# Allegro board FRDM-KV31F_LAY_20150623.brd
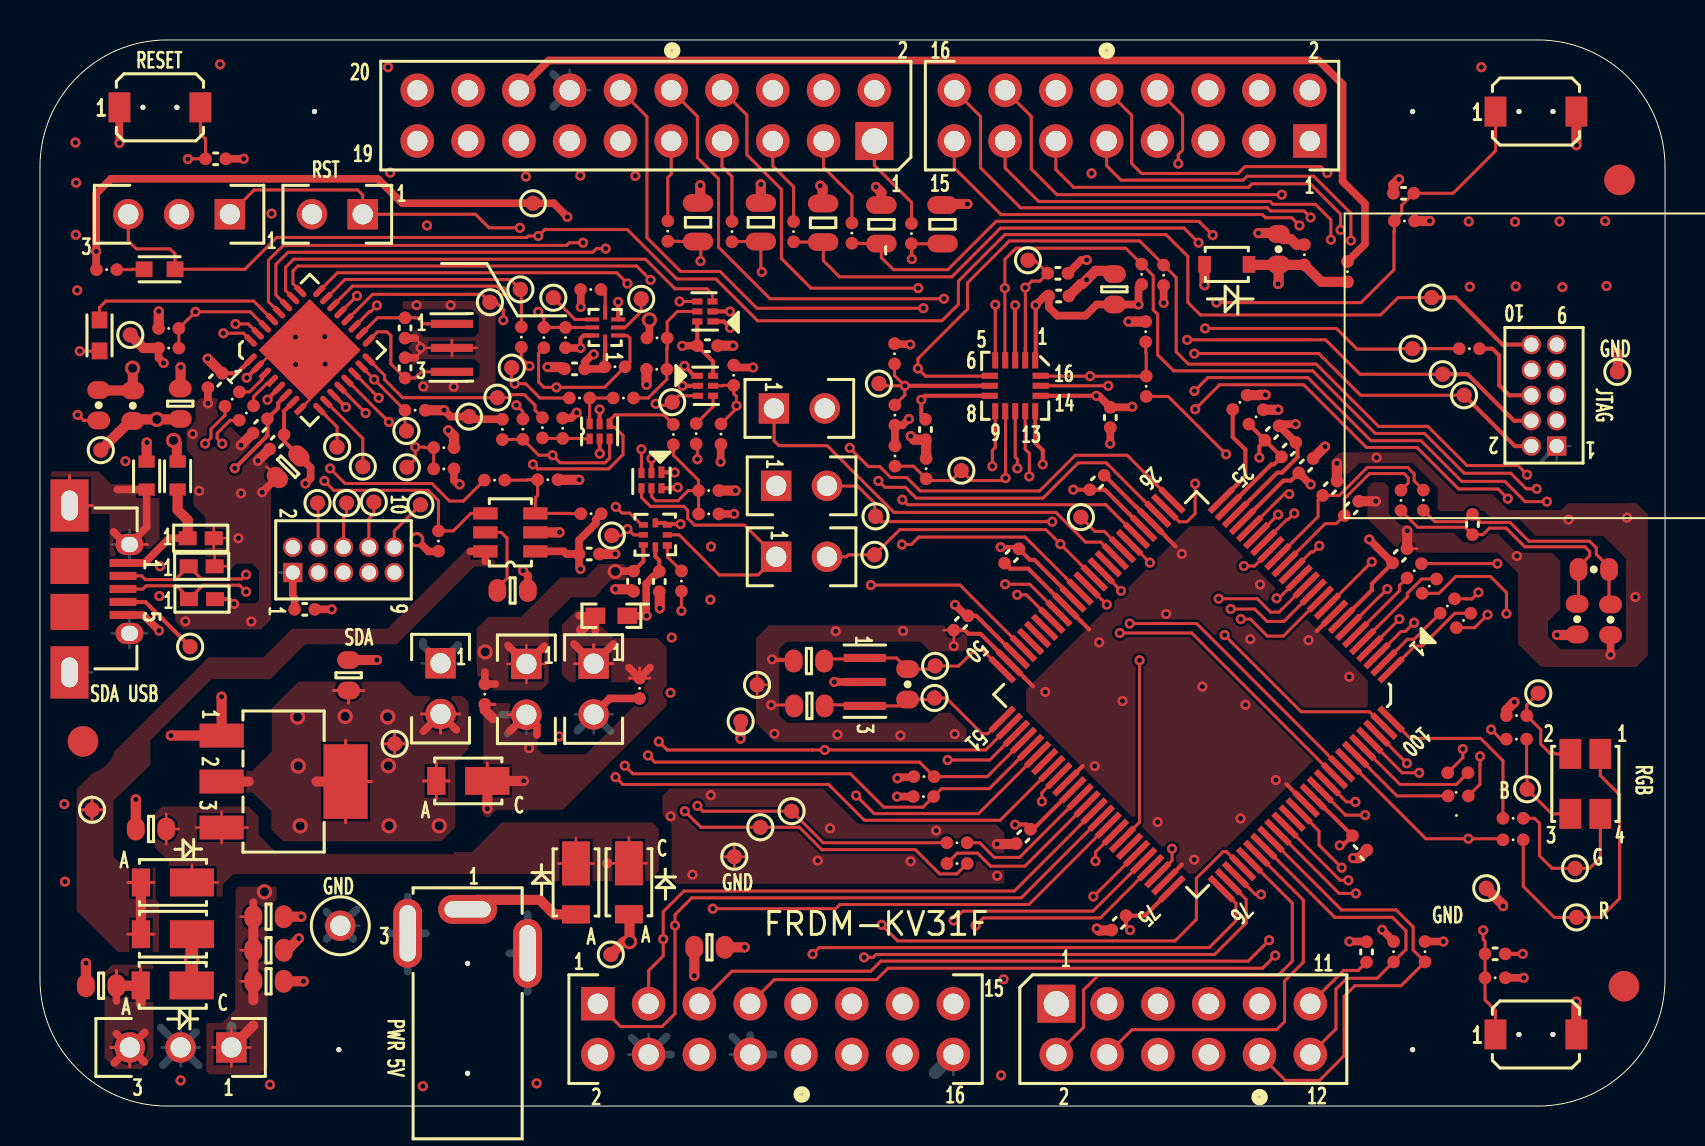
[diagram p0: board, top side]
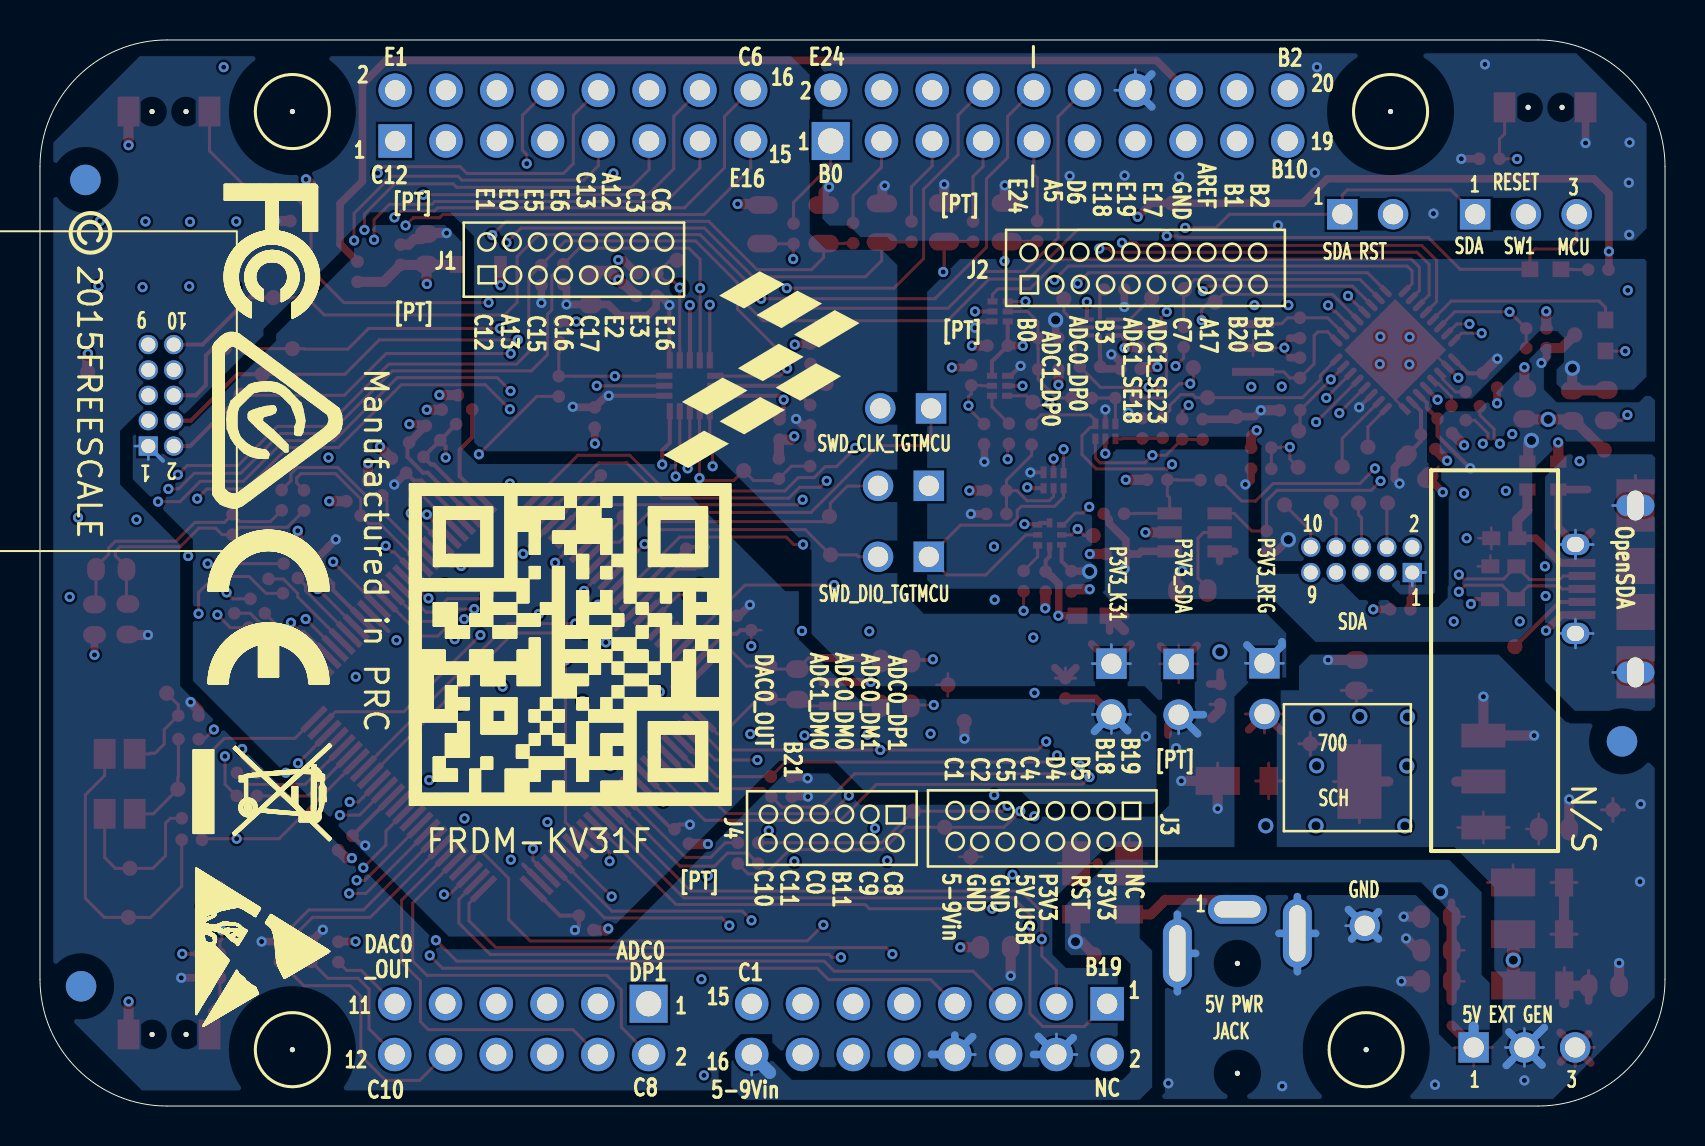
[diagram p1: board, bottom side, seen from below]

Outline 81.28 x 53.34 mm; copper layers: TOP, GND, INT_1, BOTTOM. Coordinates in mm from the lower left corner of the outline.
Outline path: 0,46.99 arc(1.86,51.48) 6.35,53.34 74.93,53.34 arc(79.42,51.48) 81.28,46.99 81.28,6.35 arc(79.42,1.86) 74.93,0 6.35,0 arc(1.86,1.86) 0,6.35 0,46.99

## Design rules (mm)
net group GA[0:7]: nets 8MHZ_EXTAL XTAL0
net group LEDRGB_BLUE: nets LEDRGB_BLUE PTE25
net group POW: nets P5V0_SDA_USB_CONN_VBUS VREFH
net group USB_SI_CONN_D: nets SDA_USB_CONN_DN SDA_USB_CONN_DP
net group USB_SI_D: nets SDA_USB_DN SDA_USB_DP
net group ANALOG: nets ADC0_DM1 ADC0_DP1 ADC1_DM1 ADC1_DP1 ADC1_SE18 DAC0_OUT PTB1 PTB10 PTC11
net group ANALOG_PH: nets PTB2 PTB3 PTB11
net group CLOCKS: nets LEDRGB_GREEN PTB18 PTC3 PTC6 PTC8 PTD1 PTE0 SDA_EXTAL SWD_CLK_TGTMCU SWD_CLK_TGTMCU_BUF
nets with their own width: min track width 0.127; nets GND

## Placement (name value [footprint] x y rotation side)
C1  10uF  [CC0402_25]  11.02 34.03 225 top
C2  1000pF  [CC0402_25]  8.79 47.39 0 top
C3  0.1UF  [CC0402_25]  50.91 41.67 0 top
C4  0.1UF  [CC0402_25]  50.95 40.53 0 top
C5  4.7uF  [CC0603_OV]  53.74 40.87 90 top
C6  22PF  [CC0402_25]  18.26 38.93 270 top
C7  0.1UF  [CC0402_25]  33.38 38.04 0 top
C8  0.1UF  [CC0402_25]  26.74 36.88 180 top
C9  22PF  [CC0402_25]  18.26 36.93 90 top
C10  0.1UF  [CC0402_25]  8.76 36.3 225 top
C11  2.2UF  [CC0603_OV]  7.02 35.14 90 top
C12  1.0UF  [CC0402_25]  11.85 33.23 225 top
C13  0.1UF  [CC0402_25]  44.29 33.85 270 top
C14  0.1UF  [CC0402_25]  53.54 34.45 270 top
C15  10uF  [CC0603_OV]  12.41 31.99 225 top
C16  0.1UF  [CC0402_25]  27.47 27.62 0 top
C17  4.7uF  [CC0402_25]  29.69 26.26 270 top
C18  0.1UF  [CC0402_25]  13.24 24.85 0 top
C19  18PF  [CC0603_OV]  23.64 25.79 180 top
C21  0.1UF  [CC0402_25]  71.65 29.1 90 top
C22  2200PF  [CC0402_25]  65.6 29.9 45 top
C23  4.7uF  [CC0402_25]  30.98 26.24 270 top
C24  0.1UF  [CC0402_25]  49.18 13.49 225 top
C25  0.1UF  [CC0402_25]  52.87 31.19 45 top
C26  0.1UF  [CC0402_25]  46.07 24.17 225 top
C27  0.1UF  [CC0402_25]  63.32 32.04 45 top
C28  0.1UF  [CC0402_25]  48.61 27.52 225 top
C29  0.1UF  [CC0402_25]  53.96 9.17 225 top
C30  0.1UF  [CC0402_25]  66.01 13.16 315 top
C32  0.01UF  [CC0402_25]  68.01 27.53 45 top
C33  0.01UF  [CC0402_25]  61.62 33.68 225 top
C34  0.1UF  [CC0402_25]  62.46 32.84 225 top
C35  2200PF  [CC0402_25]  64.52 30.91 45 top
C37  18PF  [CC0603_OV]  38.46 22.27 0 top
C38  18PF  [CC0603_OV]  38.48 20.02 0 top
C40  2.2UF  [CC0603_OV]  33.49 7.94 0 top
C41  10uF  [CC0603_OV]  5.55 13.86 180 top
C43  0.1UF  [CC0402_25]  66.35 7.71 90 top
C44  220PF  [CC0805_OV]  39.17 44.19 90 top
C50  10uF  [CC0603_OV]  11.43 9.47 0 top
C51  10uF  [CC0603_OV]  15.44 21.55 90 top
C52  10uF  [CC0603_OV]  11.43 7.79 0 top
C53  10uF  [CC0603_OV]  3.06 6.02 180 top
C54  10uF  [CC0603_OV]  11.43 6.24 0 top
C55  0.1UF  [CC0402_25]  72.79 7.61 0 top
C56  0.1UF  [CC0402_25]  68.2 45.67 180 top
C505  220PF  [CC0805_OV]  32.92 44.22 90 top
C507  220PF  [CC0805_OV]  42.09 44.12 90 top
C516  220PF  [CC0805_OV]  36.06 44.22 90 top
C522  220PF  [CC0805_OV]  45.14 44.12 90 top
D1  RED  [LED_0603]  5.98 41.87 0 top
D2  LED GREEN  [LED_0603]  2.98 38.56 90 top
D4  CLV1A-FKB-CJ1M1F1BB7R4S3  [LED4_3P4X3MM_SMT]  77.29 16.12 0 top
D5  DFLS130L-7  [POWERDI-123_3MMX2MM]  6.75 8.6 180 top
D6  DFLS130L-7  [POWERDI-123_3MMX2MM]  6.75 11.19 180 top
D7  3.0V  [SOD-323-A]  59.36 42.11 180 top
D9  DFLS130L-7  [POWERDI-123_3MMX2MM]  26.81 11.29 270 top
D10  DFLS130L-7  [POWERDI-123_3MMX2MM]  29.46 11.3 270 top
D11  DFLS130L-7  [POWERDI-123_3MMX2MM]  21.52 16.27 180 top
D13  DFLS130L-7  [POWERDI-123_3MMX2MM]  6.74 6.04 180 top
J1  CON_2X8  [HDR208_ESQ_SKT]  63.51 48.29 270 top
J2  SKT_2x10  [HDR210_ESQ_SKT]  41.73 48.29 270 top
J3  CON_2X8  [HDR208_ESQ_SKT]  27.9 5.12 90 top
J4  CON_2X6  [HDR206_ESQ_SKT]  50.84 5.12 90 top
J5  HDR 1X2 TH  [SH_HDR102_BOTTOM]  16.14 44.62 270 top
J6  MICRO USB AB 5  [CON5_MICROUSB]  1.48 25.87 270 top
J8  HDR 1X2 TH  [SH_HDR102_BOTTOM]  36.82 31.03 90 top
J9  HDR 2X5  [HDR_5X2_FTSH_TH_NSP]  75.86 33.02 180 top
J10  HDR 2X5  [HDR_5X2_FTSH_TH_NSP]  12.64 26.69 90 top
J11  HDR 1X2 TH  [SH_HDR102_BOTTOM]  36.71 34.9 90 top
J12  HDR 1X2 TH  [SH_HDR102_BOTTOM]  36.82 27.48 90 top
J18  HDR 1X2  [HDR102]  24.33 22.12 0 top
J19  HDR 1X2 TH  [SH_HDR102_BOTTOM]  20.04 22.15 0 top
J20  HDR 1X2 TH  [SH_HDR102_BOTTOM]  27.69 22.13 0 top
J24  CON PWR 3  [CON_JACK_PJ1_022_TH-RA]  21.39 9.84 90 top
J25  HDR_1X3  [HDR103]  9.5 44.62 270 top
J27  HDR_1X3  [HDR103]  9.57 2.93 270 top
L1  330 OHM  [IND_1608]  5.33 31.55 90 top
L2  330 OHM  [IND_1608]  6.88 31.55 90 top
NOREF  -  []  0 41.47 0 top
NOREF#2  -  []  65.19 -3.77 0 top
NOREF#3  -  []  65.19 -3.77 90 top
NOREF#4  -  []  28.92 39.36 90 top
NOREF#5  -  [unnamed#2]  79.23 5.99 0 top
NOREF#6  -  []  13.74 2.72 0 top
NOREF#7  -  []  70.32 0.01 90 top
NOREF#8  -  []  -16.59 -36.7 0 top
NOREF#9  -  []  -235.03 -179.13 0 top
NOREF#10  -  []  28.89 39.68 270 top
NOREF#11  -  []  39.19 48.29 0 top
NOREF#12  -  []  47.78 34.76 90 top
NOREF#13  -  []  79.64 51.25 0 top
NOREF#14  -  []  42.18 43.28 90 top
NOREF#15  -  []  47.5 36.04 90 top
NOREF#16  -  []  50.28 37.54 90 top
NOREF#17  -  []  47.78 34.76 0 top
NOREF#18  -  []  50.84 5.12 0 top
NOREF#19  -  []  18.87 48.29 90 top
NOREF#20  -  [unnamed#2]  79 46.34 0 top
NOREF#21  -  []  47.78 34.76 0 top
NOREF#22  -  []  50.84 5.12 0 top
NOREF#23  -  []  -381.97 185.27 0 top
NOREF#24  -  []  17.22 52.1 0 top
NOREF#25  -  []  47.78 34.76 0 top
NOREF#26  -  []  47.28 37.54 0 top
NOREF#27  -  []  50.26 40.54 0 top
NOREF#28  -  []  12.88 1.39 0 top
NOREF#29  -  []  24.14 10.61 0 top
NOREF#30  -  []  -408 -339.88 0 top
NOREF#31  -  []  13.74 2.72 0 top
NOREF#32  -  [unnamed#2]  2.15 18.24 0 top
NOREF#33  -  []  22.3 52.1 90 top
NOREF#34  -  []  145.04 65.17 0 top
NOREF#35  -  []  63.54 2.58 90 top
NOREF#36  -  []  28.92 38.96 270 top
NOREF#37  -  []  47.5 35.54 0 top
NOREF#38  -  []  18.87 48.29 0 top
NOREF#39  -  []  47.5 36.54 90 top
NOREF#40  -  []  54.66 12.88 180 bottom
NOREF#41  -  [unnamed#2]  13.73 49.76 180 bottom
NOREF#42  -  [unnamed#2]  68.66 2.82 180 bottom
NOREF#43  -  []  20.69 32.09 270 bottom
NOREF#44  -  []  55.65 13.45 180 bottom
NOREF#45  -  [unnamed#2]  14.95 2.82 180 bottom
NOREF#46  -  []  51.23 -43.91 270 bottom
NOREF#47  -  []  54.61 5.51 180 bottom
NOREF#48  -  []  76.38 -9.16 0 bottom
NOREF#49  -  [unnamed#2]  68.66 49.76 180 bottom
NOREF#50  -  [unnamed#2]  79.01 46.34 180 bottom
NOREF#51  -  [unnamed#2]  79.23 5.99 180 bottom
NOREF#52  -  []  91.82 39.52 180 bottom
NOREF#53  -  []  74.4 20.38 0 bottom
NOREF#54  -  [unnamed#2]  2.15 18.25 180 bottom
R1  10.0K  [RC0402_25]  68.25 44.28 180 top
R2  100  [RC0402_25]  3.34 41.85 0 top
R3  0  [RC0402_25]  24.08 38.47 90 top
R4  4.7K  [RC0402_25]  27.55 40.85 180 top
R5  4.7K  [RC0402_25]  20.2 31.88 180 top
R6  10.0K  [RC0402_25]  20.2 32.94 0 top
R7  10.0K  [RC0402_25]  6.44 38.91 180 top
R8  4.7K  [RC0402_25]  6.44 37.92 0 top
R9  4.7K  [RC0402_25]  55.1 41.62 90 top
R10  0  [RC0402_25]  25.2 38.45 90 top
R11  180K  [RC0402_25]  26.28 38.45 90 top
R12  4.7K  [RC0402_25]  30.86 38.43 0 top
R13  10.0K  [RC0402_25]  30.85 36.86 180 top
R14  10.0K  [RC0402_25]  28.76 36.99 0 top
R15  4.7K  [RC0402_25]  56.2 41.57 90 top
R16  10.0K  [RC0402_25]  34.7 36.57 90 top
R17  220  [RC0603_OV]  2.94 35.06 270 top
R18  0  [RC0402_25]  26.98 35.43 180 top
R19  0  [RC0402_25]  29.18 35.43 0 top
R20  33  [RC0402_25]  9.61 35.37 45 top
R21  10.0K  [RC0402_25]  18.76 34.81 180 top
R22  33  [RC0402_25]  10.32 34.67 45 top
R23  4.7K  [RC0402_25]  34.06 33.62 90 top
R24  0  [RC0402_25]  32.82 33.64 270 top
R25  0  [RC0402_25]  25.13 33.94 90 top
R26  10.0K  [RC0402_25]  26.14 33.91 270 top
R27  10.0K  [RC0402_25]  23.13 33.86 90 top
R28  0  [RC0402_25]  24.15 33.87 90 top
R29  1.0K  [RC0402_25]  22.74 31.32 0 top
R30  15K  [RC0402_25]  25.4 31.34 0 top
R31  10.0K  [RC0402_25]  42.74 37.64 90 top
R32  10.0K  [RC0402_25]  42.76 34.57 90 top
R33  0  [RC0402_25]  31.68 33.6 270 top
R34  10.0K  [RC0402_25]  27.56 29.64 180 top
R35  10.0K  [RC0402_25]  19.93 28.27 90 top
R36  0  [RC0603_OV]  4.64 35.04 270 top
R37  4.7K  [RC0402_25]  33.45 29.63 180 top
R38  0  [RC0402_25]  32.08 26.27 270 top
R39  10.0K  [RC0402_25]  33.45 30.79 0 top
R40  10.0K  [RC0402_25]  42.76 32.52 270 top
R41  4.7K  [RC0402_25]  44.19 15.48 0 top
R42  10.0K  [RC0402_25]  55.31 38.74 90 top
R43  10.0K  [RC0402_25]  44.32 31.89 90 top
R44  4.99K  [RC0603_OV]  78.55 24.33 270 top
R45  4.99K  [RC0603_OV]  76.89 24.36 90 top
R46  100  [RC0402_25]  69.19 30.31 270 top
R47  100  [RC0402_25]  68.07 30.3 270 top
R48  4.7K  [RC0402_25]  44.21 16.48 0 top
R49  4.7K  [RC0402_25]  69.28 7.72 270 top
R50  4.7K  [RC0402_25]  67.7 7.72 270 top
R52  1.0M  [RC0603_OV]  43.4 21.1 270 top
R53  0  [RC0402_25]  65.4 41.74 90 top
R54  0  [RC0402_25]  45.86 13.17 180 top
R55  0  [RC0402_25]  45.87 12.13 180 top
R56  0  [RC0402_25]  70.94 15.52 0 top
R57  0  [RC0402_25]  70.92 16.67 0 top
R58  0  [RC0402_25]  71.2 24.3 225 top
R59  0  [RC0402_25]  70.39 25.02 225 top
R60  0  [RC0402_25]  60.02 35.21 45 top
R61  0  [RC0402_25]  22.25 20.61 90 top
R62  0  [RC0402_25]  60.83 34.48 225 top
R63  10  [RC0402_25]  29.99 20.9 270 top
R64  0  [RC0402_25]  55.33 36.01 270 top
R65  0  [RC0402_25]  68.74 26.78 225 top
R66  1K  [RC0603_OV]  61.95 42.87 270 top
R67  0  [RC0402_25]  69.49 26.01 225 top
R68  0  [RC0402_25]  63.24 42.59 270 top
R69  576  [RC0402_25]  73.68 13.32 0 top
R73  270  [RC0402_25]  73.85 18.36 180 top
R74  270  [RC0402_25]  73.68 14.4 180 top
R75  10.0K  [RC0402_25]  72.79 6.42 180 top
R76  100  [RC0402_25]  37.69 43.75 90 top
R80  0  [RC0402_25]  71.49 37.89 180 top
R88  130  [RC0402_25]  73.86 19.54 0 top
R534  100  [RC0402_25]  31.4 43.78 90 top
R549  100  [RC0402_25]  34.61 43.75 90 top
R551  100  [RC0402_25]  40.61 43.68 90 top
R555  100  [RC0402_25]  43.59 43.65 90 top
RT1  10K  [RC0603_OV]  77.72 26.85 0 top
SH1  0  [SH0603]  28.58 24.53 180 top
SW1  SW2_STM151XX  [SW2_4X3MM_SM]  6 49.97 0 top
SW2  SW2_STM151XX  [SW2_4X3MM_SM]  74.83 49.76 0 top
SW3  SW2_STM151XX  [SW2_4X3MM_SM]  74.82 3.58 0 top
TP1  -  [TPAD_030]  24.03 40.86 0 top
TP2  -  [TPAD_030]  25.68 40.44 270 top
TP3  -  [TPAD_030]  30.07 40.39 270 top
TP4  -  [TPAD_030]  49.42 42.32 270 top
TP5  -  [TPAD_030]  18.35 31.96 0 top
TP6  -  [TPAD_030]  23.6 36.94 0 top
TP7  -  [TPAD_030]  7.51 22.98 0 top
TP8  -  [TPAD_030]  41.96 36.15 270 top
TP9  -  [TPAD_030]  16.15 31.99 0 top
TP10  -  [TPAD_030]  14.86 32.97 0 top
TP11  -  [TPAD_030]  46.08 31.79 270 top
TP12  -  [TPAD_030]  4.52 38.58 0 top
TP13  -  [TPAD_030]  76.86 9.44 270 top
TP14  -  [TPAD_030]  74.38 15.85 270 top
TP15  -  [TPAD_030]  3.04 32.82 0 top
TP16  TEST POINT WHITE  [TEST_LOOP]  15.02 9.02 0 top
TP17  -  [TPAD_030]  76.78 11.89 270 top
TP18  -  [TPAD_030]  52.06 29.47 0 top
TP19  -  [TPAD_030]  2.6 14.82 0 top
TP20  -  [TPAD_030]  28.55 7.58 0 top
TP21  -  [TPAD_030]  35.87 21.07 0 top
TP22  -  [TPAD_030]  72.34 10.9 0 top
TP23  -  [TPAD_030]  78.89 36.73 0 top
TP24  -  [TPAD_030]  34.73 12.47 0 top
TP25  -  [TPAD_030]  18.33 33.78 0 top
TP26  -  [TPAD_030]  13.88 30.17 0 top
TP27  -  [TPAD_030]  15.33 30.17 0 top
TP28  -  [TPAD_030]  16.7 30.21 0 top
TP29  -  [TPAD_030]  19.03 30.08 0 top
TP30  -  [TPAD_030]  71.23 35.56 0 top
TP31  -  [TPAD_030]  70.16 36.62 0 top
TP32  -  [TPAD_030]  68.65 37.89 0 top
TP33  -  [TPAD_030]  69.61 40.45 0 top
TP35  -  [TPAD_030]  44.78 22.02 0 top
TP36  -  [TPAD_030]  44.74 20.42 0 top
TP37  -  [TPAD_030]  35.05 19.25 0 top
TP38  -  [TPAD_030]  21.46 34.5 0 top
TP39  -  [TPAD_030]  37.59 14.75 0 top
TP40  -  [TPAD_030]  36.03 13.95 0 top
TP41  -  [TPAD_030]  41.74 27.58 0 top
TP42  -  [TPAD_030]  41.79 29.5 0 top
TP43  -  [TPAD_030]  74.94 20.65 0 top
TP44  -  [TPAD_030]  24.66 45.17 0 top
TP48  -  [TPAD_030]  28.6 28.54 0 top
TP49  -  [TPAD_030]  31.62 35.22 0 top
TP50  -  [TPAD_030]  22.5 40.22 0 top
TP52  -  [TPAD_030]  22.88 35.44 0 top
TP56  -  [TPAD_030]  17.74 18.13 0 top
U1  0402ESDA-MLP  [0402_MLP]  8.04 28.41 0 top
U2  74LVCH1T45  [UDFN6_1X1P5MM]  33.26 39.76 180 top
U3  NTSX2102GU8H  [XQFN8_1P45X1P25MM]  28.27 38.96 90 top
U4  0402ESDA-MLP  [0402_MLP]  8.09 27.01 0 top
U5  MK20DX128VFM5  [QFN32_S142EP]  13.49 37.83 45 top
U6  0402ESDA-MLP  [0402_MLP]  8.1 25.36 0 top
U7  74LVCH1T45  [UDFN6_1X1P5MM]  33.28 36.04 0 top
U8  FXOS8700CQ  [QFN5X3_0P5_3X3]  48.78 36.04 270 top
U9  NLX2G14  [ULLGA6_1P45X1_0P5MM]  27.99 33.76 90 top
U10  74LVC2T45GM,125  [QFN8_1P6X1P6MM]  30.78 28.58 180 top
U11  MIC2005-0.8YM6  [SOT23-6_A]  23.53 28.7 180 top
U12  74LVCH1T45  [UDFN6_1X1P5MM]  30.58 31.29 270 top
U13  MKV31F512VLL12  [LQFP100_0P5_14X14]  57.85 20.59 225 top
U17  NCP1117ST33T3G  [SOT223]  12.18 16.24 270 top
X501  8.00MHZ  [XTAL3_3P35X1P45_SM]  41.25 21.22 90 top
Y1  8.00MHZ  [XTAL3_3P35X1P45_SM]  20.6 37.93 90 top

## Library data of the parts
C1-C6 C9 C11-C14 C21 C22 C35 C40 C41 C44 C50-C56 C505 C507 C516 C522 = CAP_NP
C7 C8 C10 C15-C18 C23-C30 C34 C43 = CAP_NP: tolerance: 10%
C19 C37 C38 = CAP_NP: tolerance: 5%
C32 C33 = CAP_NP: tolerance: 20%
D1 D2 = LED
D4 = CLV1A_LED_4P
D5 D6 D9-D11 D13 = DIODE_SCHTKY
D7 = ZDIODE
J1 J3 = CONN_HDR_8X2
J2 = CONN_HDR_10X2
J4 = CONN_HDR_6X2
J5 J8 J11 J12 J18-J20 = CONN_HDR_2X1
J6 = USB_MINI_AB_RECEPTACLE
J9 J10 = CONN_HDR_5X2
J24 = DC POWER JACK
J25 J27 = CONN_HDR_3X1
L1 L2 = BEAD
R1 R2 R4 R5 R8 R9 R12 R15 R23 R29 R30 R34 R35 R37 R41 R48-R50 R54-R59 R65 R67 R75 R76 R534 R549 R551 R555 = RES: tolerance: 1%
R3 R6 R7 R11 R17-R22 R25 R28 R31-R33 R36 R40 R42-R47 R53 R60-R64 R66 R68 R69 R74 R80 R88 = RES
R10 R13 R14 R16 R24 R26 R27 R38 R39 R52 = RES: tolerance: 5%
R73 = RES: signal model: DEFAULT_RESISTOR_330.000000OHM_2_1
RT1 = THERMISTOR
SH1 = RES_SHORT-2
SW1-SW3 = SW2_STM151XX
TP1-TP33 TP35-TP44 TP48-TP50 TP52 TP56 = TestLoop
U1 U4 U6 = DIODE_TVS_BIDIR
U2 U7 U12 = 74LVCH1T45_6P
U3 = NTSX2102GU8H_8P
U5 = PK20DX128V_QFN_32P
U8 = FXOS8700CQ_QFN_16P
U9 = NLU2GU04
U10 = 74LVC2T45GM_8P
U11 = MIC2005-0.8YM6
U13 = MKV10FN_LQFP_100P
U17 = LD1117AS18
X501 Y1 = XTAL_CS

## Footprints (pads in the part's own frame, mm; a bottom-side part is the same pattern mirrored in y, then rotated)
0402_MLP
  rect 0.9x0.7 smd: 1(-0.65,0) 2(0.65,0)
CC0402_25
  round 0.635 smd: 1(-0.508,0) 2(0.508,0)
CC0603_OV
  oval 0.889x1.143 smd: 1(-0.762,0) 2(0.762,0)
CC0805_OV
  oval 0.889x1.524 smd: 1(-0.965,0) 2(0.965,0)
CON5_MICROUSB
  rect 1.803x1.905 smd: (-1.15,0) (1.15,0)
  rect 0.406x1.346 smd: 1(-1.3,2.675) 2(-0.65,2.675) 3(0,2.675) 4(0.65,2.675) 5(1.3,2.675)
  oval 1.067x1.397 hole 0.762x0.864: S1(-2.225,3) S2(2.225,3)
  rect 2.616x1.905 hole 1.499x0.838: S3(-4.175,0) S4(4.175,0)
CON_JACK_PJ1_022_TH-RA
  round 0.254 hole 1.6 unplated: (-8.2,0) (-2.7,0)
  oval 1.448x2.946 hole 0.813x2.311: 1(0,0)
  oval 3.454x1.448 hole 2.819x0.813: 2(-2.2,-3) 3(-1.2,3)
HDR102
  rect 1.524x1.524 hole 1.016: 1(0,0)
  round 1.524 hole 1.016: 2(0,-2.54)
HDR103
  rect 1.524x1.524 hole 1.016: 1(0,0)
  round 1.524 hole 1.016: 2(0,-2.54) 3(0,-5.08)
HDR206_ESQ_SKT
  rect 1.905x1.905 hole 1.27: 1(0,0)
  round 1.676 hole 1.016: 2(-2.54,0) 3(0,-2.54) 4(-2.54,-2.54) 5(0,-5.08) 6(-2.54,-5.08) 7(0,-7.62) 8(-2.54,-7.62) 9(0,-10.16) 10(-2.54,-10.16) 11(0,-12.7) 12(-2.54,-12.7)
HDR208_ESQ_SKT
  rect 1.676x1.676 hole 1.016: 1(0,0)
  round 1.676 hole 1.016: 2(-2.54,0) 3(0,-2.54) 4(-2.54,-2.54) 5(0,-5.08) 6(-2.54,-5.08) 7(0,-7.62) 8(-2.54,-7.62) 9(0,-10.16) 10(-2.54,-10.16) 11(0,-12.7) 12(-2.54,-12.7) 13(0,-15.24) 14(-2.54,-15.24) 15(0,-17.78) 16(-2.54,-17.78)
HDR210_ESQ_SKT
  rect 1.905x1.905 hole 1.27: 1(0,0)
  round 1.676 hole 1.016: 2(-2.54,0) 3(0,-2.54) 4(-2.54,-2.54) 5(0,-5.08) 6(-2.54,-5.08) 7(0,-7.62) 8(-2.54,-7.62) 9(0,-10.16) 10(-2.54,-10.16) 11(0,-12.7) 12(-2.54,-12.7) 13(0,-15.24) 14(-2.54,-15.24) 15(0,-17.78) 16(-2.54,-17.78) 17(0,-20.32) 18(-2.54,-20.32) 19(0,-22.86) 20(-2.54,-22.86)
HDR_5X2_FTSH_TH_NSP
  rect 0.965x0.965 hole 0.711: 1(0,0)
  round 0.965 hole 0.711: 2(1.27,0) 3(0,-1.27) 4(1.27,-1.27) 5(0,-2.54) 6(1.27,-2.54) 7(0,-3.81) 8(1.27,-3.81) 9(0,-5.08) 10(1.27,-5.08)
IND_1608
  rect 0.61x0.813 smd: 1(-0.7,0) 2(0.7,0)
LED4_3P4X3MM_SMT
  rect 1.092x1.499 smd: 1(0.75,1.5) 2(-0.75,1.5) 3(-0.75,-1.5) 4(0.75,-1.5)
LED_0603
  rect 0.838x0.787 smd: A(-0.775,0) C(0.775,0)
LQFP100_0P5_14X14
  rect 1.651x0.305 smd: 1(-7.75,6) 2(-7.75,5.5) 3(-7.75,5) 4(-7.75,4.5) 5(-7.75,4) 6(-7.75,3.5) 7(-7.75,3) 8(-7.75,2.5) 9(-7.75,2) 10(-7.75,1.5) 11(-7.75,1) 12(-7.75,0.5) 13(-7.75,0) 14(-7.75,-0.5) 15(-7.75,-1) 16(-7.75,-1.5) 17(-7.75,-2) 18(-7.75,-2.5) 19(-7.75,-3) 20(-7.75,-3.5) 21(-7.75,-4) 22(-7.75,-4.5) 23(-7.75,-5) 24(-7.75,-5.5) 25(-7.75,-6) 51(7.75,-6) 52(7.75,-5.5) 53(7.75,-5) 54(7.75,-4.5) 55(7.75,-4) 56(7.75,-3.5) 57(7.75,-3) 58(7.75,-2.5) 59(7.75,-2) 60(7.75,-1.5) 61(7.75,-1) 62(7.75,-0.5) 63(7.75,0) 64(7.75,0.5) 65(7.75,1) 66(7.75,1.5) 67(7.75,2) 68(7.75,2.5) 69(7.75,3) 70(7.75,3.5) 71(7.75,4) 72(7.75,4.5) 73(7.75,5) 74(7.75,5.5) 75(7.75,6)
  rect 0.305x1.651 smd: 26(-6,-7.75) 27(-5.5,-7.75) 28(-5,-7.75) 29(-4.5,-7.75) 30(-4,-7.75) 31(-3.5,-7.75) 32(-3,-7.75) 33(-2.5,-7.75) 34(-2,-7.75) 35(-1.5,-7.75) 36(-1,-7.75) 37(-0.5,-7.75) 38(0,-7.75) 39(0.5,-7.75) 40(1,-7.75) 41(1.5,-7.75) 42(2,-7.75) 43(2.5,-7.75) 44(3,-7.75) 45(3.5,-7.75) 46(4,-7.75) 47(4.5,-7.75) 48(5,-7.75) 49(5.5,-7.75) 50(6,-7.75) 76(6,7.75) 77(5.5,7.75) 78(5,7.75) 79(4.5,7.75) 80(4,7.75) 81(3.5,7.75) 82(3,7.75) 83(2.5,7.75) 84(2,7.75) 85(1.5,7.75) 86(1,7.75) 87(0.5,7.75) 88(0,7.75) 89(-0.5,7.75) 90(-1,7.75) 91(-1.5,7.75) 92(-2,7.75) 93(-2.5,7.75) 94(-3,7.75) 95(-3.5,7.75) 96(-4,7.75) 97(-4.5,7.75) 98(-5,7.75) 99(-5.5,7.75) 100(-6,7.75)
POWERDI-123_3MMX2MM
  rect 0.914x1.397 smd: A(1.7,0)
  rect 2.21x1.397 smd: C(-0.85,0)
QFN5X3_0P5_3X3
  rect 0.813x0.305 smd: 1(-1.275,1) 2(-1.275,0.5) 3(-1.275,0) 4(-1.275,-0.5) 5(-1.275,-1) 9(1.275,-1) 10(1.275,-0.5) 11(1.275,0) 12(1.275,0.5) 13(1.275,1)
  rect 0.305x0.813 smd: 6(-0.5,-1.275) 7(0,-1.275) 8(0.5,-1.275) 14(0.5,1.275) 15(0,1.275) 16(-0.5,1.275)
QFN8_1P6X1P6MM
  rect 0.457x0.33 smd: 1(-0.6,0.525)
  rect 0.457x0.279 smd: 2(-0.6,0) 3(-0.6,-0.5) 5(0.6,-0.5) 6(0.6,0) 7(0.6,0.5)
  rect 0.279x0.457 smd: 4(0,-0.6) 8(0,0.6)
QFN32_S142EP
  custom 0.07x0.07 smd: 1(-2.4,1.751) 2(-2.4,1.251) 3(-2.4,0.751) 4(-2.4,0.25) 5(-2.4,-0.25) 6(-2.4,-0.751) 7(-2.4,-1.251) 8(-2.4,-1.751) 9(-1.751,-2.4) 10(-1.251,-2.4) 11(-0.751,-2.4) 12(-0.25,-2.4) 13(0.25,-2.4) 14(0.751,-2.4) 15(1.251,-2.4) 16(1.751,-2.4) 17(2.4,-1.751) 18(2.4,-1.251) 19(2.4,-0.751) 20(2.4,-0.25) 21(2.4,0.25) 22(2.4,0.751) 23(2.4,1.251) 24(2.4,1.751) 25(1.751,2.4) 26(1.251,2.4) 27(0.751,2.4) 28(0.25,2.4) 29(-0.25,2.4) 30(-0.751,2.4) 31(-1.251,2.4) 32(-1.751,2.4)
  rect 3.607x3.607 smd: 33(0,0)
RC0402_25
  round 0.635 smd: 1(-0.508,0) 2(0.508,0)
RC0603_OV
  oval 0.889x1.143 smd: 1(-0.762,0) 2(0.762,0)
SH0603
  rect 0.991x0.813 smd: 1(-0.8,0) 2(0.8,0)
SH_HDR102_BOTTOM
  rect 1.524x1.524 hole 1.016: 1(0,0)
  round 1.524 hole 1.016: 2(0,-2.54)
SOD-323-A
  rect 0.635x0.838 smd: A(1.115,0) C(-1.115,0)
SOT23-6_A
  rect 1.219x0.61 smd: 1(-1.25,0.95) 2(-1.25,0) 3(-1.25,-0.95) 4(1.25,-0.95) 5(1.25,0) 6(1.25,0.95)
SOT223
  rect 1.194x2.21 smd: 1(-2.3,-3.1) 2(0,-3.1) 3(2.3,-3.1)
  rect 3.734x2.21 smd: 4(0,3.1)
SW2_4X3MM_SM
  round 0.254 hole 0.711 unplated: (-0.85,0) (0.85,0)
  rect 1.092x1.499 smd: 1(-2.025,0) 2(2.025,0)
TEST_LOOP
  round 1.524 hole 1.016: 1(0,0)
TPAD_030
  round 0.762 smd: 1(0,0)
UDFN6_1X1P5MM
  rect 0.584x0.305 smd: 1(-0.418,0.5)
  rect 0.508x0.305 smd: 2(-0.38,0) 3(-0.38,-0.5) 4(0.38,-0.5) 5(0.38,0) 6(0.38,0.5)
ULLGA6_1P45X1_0P5MM
  rect 0.533x0.305 smd: 1(-0.375,0.5) 2(-0.375,0) 3(-0.375,-0.5) 4(0.375,-0.5) 5(0.375,0) 6(0.375,0.5)
unnamed#2
  round 1.524 smd: (0,0)
XQFN8_1P45X1P25MM
  rect 0.787x0.203 smd: 1(-0.75,0)
  rect 0.203x0.711 smd: 2(-0.4,-0.65) 3(0,-0.65) 4(0.4,-0.65) 6(0.4,0.65) 7(0,0.65) 8(-0.4,0.65)
  rect 0.711x0.203 smd: 5(0.75,0)
XTAL3_3P35X1P45_SM
  rect 0.406x2.108 smd: 1(1.2,0) 2(0,0) 3(-1.2,0)

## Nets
GND: C1.2 C2.2 C3.2 C4.2 C5.2 C6.2 C7.2 C8.2 C9.2 C10.2 C11.2 C12.2 C13.2 C14.2 C15.2 C16.2 C17.2 C18.2 C22.2 C23.2 C24.2 C25.2 C26.2 C27.2 C28.2 C29.2 C30.2 C32.2 C35.2 C37.1 C38.1 C40.2 C41.2 C43.2 C44.2 C50.2 C51.2 C52.2 C53.2 C54.2 C55.2 C56.2 C505.2 C507.2 C516.2 C522.2 D7.A(ANODE) J2.14 J3.12(B6) J3.14(B7) J6.5(P5) J9.3(A2) J9.5(A3) J10.3(A2) J10.5(A3) J24.2 J24.3 J27.2 L1.2 R6.2 R7.2 R13.2 R16.2 R30.2 R31.2 R39.2 R42.2 R43.2 R44.2 R60.2 R62.1 SW1.1(SW1) SW2.2(SW2) SW3.2(SW2) TP16.1(PIN1) TP21.1(PIN1) TP22.1(PIN1) TP23.1(PIN1) TP24.1(PIN1) U1.2(A2) U2.2(GND) U3.4(GND) U4.2(A2) U5.2(VSS1) U5.8(VSSA) U5.33(EPAD) U6.2(A2) U7.2(GND) U8.3(RSVD1) U8.5(GND1) U8.12(GND2) U8.13(RSVD2) U9.2(GND) U10.3(DIR) U10.4(GND) U11.2(GND) U12.2(GND) U13.9(VSS1) U13.29(VSS2) U13.41(VSS3) U13.49(VSS4) U13.60(VSS5) U13.74(VSS6) U13.88(VSS7) U17.1(GND) X501.2 Y1.2
P3V3: C4.1 C5.1 C14.1 C40.1 D11.C J3.4(B2) J3.8(B4) J18.2 J19.1 J20.1 R1.1 R9.1 R15.1 R32.1 R40.1 R41.1 R45.1 R48.1 R49.1 R50.1 R61.1 R63.1 R75.1 R88.1 SH1.2 U8.1(VDDIO) U8.14(VDD)
P3V3_KV31: C24.1 C25.1 C26.1 C27.1 C28.1 C29.1 C30.1 C32.1 J9.1(A1) J20.2 R63.2 R66.1 R68.1 TP37.1(PIN1) U13.8(VDD1) U13.22(VDDA) U13.30(VDD2) U13.40(VDD3) U13.48(VDD4) U13.61(VDD5) U13.75(VDD6) U13.89(VDD7)
P3V3_SDA: C8.1 C10.1 C12.1 C15.1 C17.1 C18.1 J10.1(A1) J18.1 R4.2 R12.1 R14.1 R17.1 R21.1 R23.1 R26.1 R27.2 R35.1 R36.1 R37.1 R61.2 TP38.1(PIN1) U2.1(VCCA) U3.1(VCCA) U5.1(VDD1) U5.7(VDDA) U5.11(VBAT) U7.1(VCCA) U9.5(VCC) U10.7(VCCA) U12.1(VCCA)
P3V3_VREG: C51.1 D11.A J19.2 TP56.1(PIN1) U17.2(VOUT) U17.4(TAB)
P5V0_SDA_USB_CONN_VBUS: J6.1(P1) L2.1 U1.1(A1)
P5V_OPT_VR: C53.1 D13.A J27.3
P5V_SDA: C1.1 C16.1 C19.1 L2.2 R5.1 R8.1 R34.1 TP12.1(PIN1) U5.6(VREGIN) U11.1(VIN)
P5V_SDA_PSW: D5.A D6.A TP19.1(PIN1) U11.6(VOUT)
P5V_USB: D5.C D13.C J3.10(B5)
VSSA: R60.1 U13.25(VSSA)
8MHZ_EXTAL: C37.2 R52.1 TP35.1(PIN1) U13.50(PTA18/EXTAL0/FTM0_FLT2/FTM_CLKI) X501.1
ADC0_DM0: J4.5(A3) U13.19(ADC0_DM0/ADC1_DM3)
ADC0_DM1: J4.3(A2) U13.15(ADC0_DM1)
ADC0_DP0: C44.1 R76.1 U13.18(ADC0_DP0/ADC1_DP3)
ADC0_DP0_RC: J2.5 R76.2
ADC0_DP1: J4.1(A1) U13.14(ADC0_DP1)
ADC1_DM0: J4.7(A4) U13.21(ADC1_DM0/ADC0_DM3)
ADC1_DM1: C35.1 R46.1 U13.17(ADC1_DM1/ADC0_DM2)
ADC1_DP0: C507.1 R551.1 U13.20(ADC1_DP0/ADC0_DP3)
ADC1_DP0_RC: J2.3 R551.2
ADC1_DP1: C22.1 R47.1 U13.16(ADC1_DP1/ADC0_DP2)
ADC1_SE18: C505.1 R534.1 U13.26(VREF_OUT/CMP1_IN5/CMP0_IN5/ADC1)
ADC1_SE18_RC: J2.9 R534.2
ADC1_SE23: J2.11 U13.28(DAC1_OUT/CMP0_IN4/ADC1_SE23)
AREF: J2.16 R53.2
DAC0_OUT: C43.1 J4.11(A6) U13.27(DAC0_OUT/CMP1_IN3/ADC0_SE23)
DC_JACK: D9.A J24.1(PIN)
FXOS8700CQ_CRST: C13.1 U8.8(CRST)
FXOS8700CQ_I2C_SA0: R31.1 R32.2 TP8.1(PIN1) U8.7(SA0/MISO)
FXOS8700CQ_I2C_SA1: R40.2 R43.1 TP11.1(PIN1) U8.10(SA1/C\S\)
I2C0_SCL_PKYK: R56.1 U13.95(PTD2/LLWU_P13/SPI0_SOUT/UART2_R)
I2C0_SDA_PKYK: R57.2 U13.96(PTD3/SPI0_SIN/UART2_TX/FTM3_CH3)
JTAG_TDI: U13.35(PTA1/UART0_RX/FTM0_CH6/CMP0_OUT)
LEDRGB_BLUE: D4.3(BLUE_C) R73.1 TP14.1(PIN1)
LEDRGB_GREEN: D4.4(GREEN_C) R74.1 TP17.1(PIN1)
LEDRGB_RED: D4.1(RED_C) R69.2 TP13.1(PIN1)
LVLRST_EN: R4.1 U3.5(OE)
MIC2005_CSLEW: C19.2 U11.5(CSLEW)
MMA8451_BYP: C3.1 TP4.1(PIN1) U8.2(BYP)
P5-9V_VIN: C50.1 C52.1 C54.1 D10.A J3.16(B8) J27.1 TP20.1(PIN1)
P5-9V_VIN_VR: C41.1 D6.C D9.C D10.C U17.3(VIN)
POWER_EN: R29.1 U5.31(ADC0_SE7B/PTD6/SPI0_PCS3/UART0_)
PTA2: R80.2 TP32.1(PIN1) U13.36(PTA2/UART0_TX/FTM0_CH7/CMP1_OUT)
PTA4: C56.1 R1.2 SW2.1(SW1) U13.38(PTA4/LLWU_P3/FTM0_CH1/FTM0_FLT3)
PTA5: J2.4 U13.39(PTA5/FTM0_CH2/J\T\A\G\_\T\R\S\T)
PTA12: J1.12(B6) U13.42(PTA12/FTM1_CH0/FTM1_QD_PHA)
PTA13: J1.3(A2) U13.43(PTA13/LLWU_P4/FTM1_CH1/FTM1_QD_)
PTA17: J2.15 U13.47(PTA17/ADC1_SE17/SPI0_SIN/U\A\R\)
PTB0: C522.1 R555.1 U13.53(PTB0/LLWU_P5/ADC0_SE8/ADC1_SE8/)
PTB0_RC: J2.1 R555.2
PTB1: J2.18 R48.2 U13.54(PTB1/ADC0_SE9/ADC1_SE9/I2C0_SDA)
PTB2: J2.20 R41.2 U13.55(PTB2/ADC0_SE12/I2C0_SCL/U\A\R\T)
PTB3: C516.1 R549.1 U13.56(PTB3/ADC0_SE13/I2C0_SDA/U\A\R\T)
PTB3_RC: J2.7 R549.2
PTB10: J2.19 U13.58(PTB10/ADC1_SE14/SPI1_PCS0/LPUAR)
PTB11: J4.6(B3) U13.59(PTB11/ADC1_SE15/SPI1_SCK/LPUART)
PTB18: J3.3(A2) U13.64(PTB18/FTM2_CH0/FBA_AD15/FTM2_QD)
PTB19: J3.1(A1) U13.65(PTB19/FTM2_CH1/F\B\A\_\O\E\/FTM)
PTB20: J2.17 U13.66(PTB20/FBA_AD31/CMP0_OUT)
PTB21: J4.9(A5) U13.67(PTB21/FBA_AD30/CMP1_OUT)
PTB22: R64.2 U13.68(PTB22/FBA_AD29)
PTC0: J4.8(B4) U13.70(PTC0/ADC0_SE14/SPI0_PCS4/PDB0_E)
PTC1: J3.15(A8) U13.71(PTC1/LLWU_P6/ADC0_SE15/SPI0_PCS)
PTC2: J3.13(A7) U13.72(PTC2/ADC0_SE4B/CMP1_IN0/SPI0_PC)
PTC3: J1.14(B7) U13.73(PTC3/LLWU_P7/CMP1_IN1/SPI0_PCS1)
PTC4: J3.9(A5) U13.76(PTC4/LLWU_P8/SPI0_PCS0/UART1_TX)
PTC5: J3.11(A6) U13.77(PTC5/LLWU_P9/SPI0_SCK/LPTMR0_AL)
PTC6: J1.16(B8) U13.78(PTC6/LLWU_P10/CMP0_IN0/SPI0_SOU)
PTC7: J2.13 U13.79(PTC7/CMP0_IN1/SPI0_SIN/FBA_AD8/)
PTC8: J4.2(B1) U13.80(PTC8/ADC1_SE4B/CMP0_IN2/FTM3_CH)
PTC9: J4.4(B2) U13.81(PTC9/ADC1_SE5B/CMP0_IN3/FTM3_CH)
PTC10: J4.12(B6) R50.2 U13.82(PTC10/ADC1_SE6B/I2C1_SCL/FTM3_C)
PTC11: J4.10(B5) R49.2 U13.83(PTC11/LLWU_P11/ADC1_SE7B/I2C1_S)
PTC12: J1.1(A1) U13.84(PTC12/FBA_AD27/FTM3_FLT0)
PTC13: J1.10(B5) U13.85(PTC13/FBA_AD26)
PTC15: J1.5(A3) U13.87(PTC15/FBA_AD24)
PTC16: J1.7(A4) U13.90(PTC16/LPUART0_RX/F\B\A\_\C\S\5\)
PTC17: J1.9(A5) U13.91(PTC17/LPUART0_TX/F\B\A\_\C\S\4\)
PTC18: U8.9(INT2) U13.92(PTC18/L\P\U\A\R\T\0\_\R\T\S\/F\)
PTD0: U8.11(INT1) U13.93(PTD0/LLWU_P12/SPI0_PCS0/U\A\R\T)
PTD1: R69.1 U13.94(PTD1/ADC0_SE5B/SPI0_SCK/U\A\R\T)
PTD2: R9.2 R56.2 U8.4(SCL/SCLK)
PTD3: R15.2 R57.1 U8.6(SDA/MOSI)
PTD4: J3.7(A4) U13.97(PTD4/LLWU_P14/SPI0_PCS1/U\A\R\T)
PTD5: J3.5(A3) U13.98(PTD5/ADC0_SE6B/SPI0_PCS2/U\A\R\)
PTD6: J2.6 U13.99(PTD6/LLWU_P15/ADC0_SE7B/SPI0_PC)
PTD7: R74.2 U13.100(PTD7/UART0_TX/FTM0_CH7/FTM0_FLT)
PTE0: J1.4(B2) R58.2
PTE1: J1.2(B1) R59.1
PTE2: J1.11(A6) U13.3(PTE2/LLWU_P1/ADC1_SE6A/SPI1_SCK)
PTE3: J1.13(A7) U13.4(PTE3/ADC1_SE7A/SPI1_SIN/U\A\R\T)
PTE4: C55.1 R67.2 R75.2 SW3.1(SW1)
PTE5: J1.6(B3) R65.1
PTE6: J1.8(B4) U13.7(PTE6/SPI1_PCS3/L\P\U\A\R\T\0\_\)
PTE16: J1.15(A8) U13.10(PTE16/ADC0_SE4A/SPI0_PCS0/UART2)
PTE17: J2.12 U13.11(PTE17/ADC0_SE5A/SPI0_SCK/UART2_)
PTE18: J2.8 U13.12(PTE18/ADC0_SE6A/SPI0_SOUT/U\A\R)
PTE19: J2.10 U13.13(PTE19/ADC0_SE7A/SPI0_SIN/U\A\R\)
PTE24: J2.2 U13.31(PTE24/ADC0_SE17/FTM0_CH0/I2C0_S)
PTE25: R73.2 U13.32(PTE25/ADC0_SE18/FTM0_CH1/I2C0_S)
RST_TGTMCU_B: D1.C(CATHODE) J3.6(B3) J9.10(B5) J25.3 R10.2 R11.2 TP33.1(PIN1) U3.7(B1) U13.52(R\E\S\E\T\)
SDA_EXTAL: C9.1 U5.17(EXTAL0/PTA18/FTM0_FLT2/FTM_CLKI) Y1.3
SDA_JTAG_TCLK: J10.4(B2) TP26.1(PIN1) U5.12(JTAG_TCLK/SWD_CLK/EZP_CLK/TSI0_)
SDA_JTAG_TDI: J10.8(B4) TP28.1(PIN1) U5.13(JTAG_TDI/EZP_DI/TSI0_CH2/PTA1/U)
SDA_JTAG_TDO: J10.6(B3) TP27.1(PIN1) U5.14(JTAG_TDO/TRACE_SWO/EZP_DO/TSI0_)
SDA_JTAG_TMS: J10.2(B1) R21.2 TP25.1(PIN1) U5.15(JTAG_TMS/SWD_DIO/TSI0_CH4/PTA3/)
SDA_LED: D2.C(CATHODE) U5.29(PTD4/SPI0_PCS1/U\A\R\T\0\_\R\T\)
SDA_LED_R: D2.A(ANODE) R17.2
SDA_RST: J10.10(B5) R5.2 R6.1 TP5.1(PIN1) TP29.1(PIN1) U5.19(R\E\S\E\T\)
SDA_RST_LED: D1.A(ANODE) R2.2
SDA_RST_TGTMCU_B: J5.2 U5.21(ADC0_SE9/TSI0_CH6/PTB1/I2C0_SDA)
SDA_RST_TGTMCU_J_B: J5.1 J25.1 R10.1 R14.2 U3.2(A1)
SDA_RX_EN: R16.1 R23.2 U7.5(DIR)
SDA_SPI0_CS: R3.2 TP1.1(PIN1) U5.23(ADC0_SE4B/CMP1_IN0/TSI0_CH15/PT)
SDA_SPI0_RST_B: R18.2 TP6.1(PIN1) U5.22(ADC0_SE15/TSI0_CH14/PTC1/SPI0_P)
SDA_SPI0_SCK: U2.3(A) U5.26(PTC5/SPI0_SCK/LPTMR0_ALT2/I2S0_)
SDA_SPI0_SIN: U5.28(CMP0_IN1/PTC7/SPI0_SIN/USB_SOF_) U10.5(2A)
SDA_SPI0_SOUT: U5.27(CMP0_IN0/PTC6/SPI0_SOUT/PDB0_EX) U12.3(A)
SDA_SWD_EN: R18.1 R19.1 U9.6(Y\2\)
SDA_SWD_EN_B: R25.2 TP52.1(PIN1) U5.16(N\M\I\/E\Z\P\_\C\S\/TSI0_CH5/PT)
SDA_SWD_EN_B_R: R25.1 R26.2 U9.1(A1)
SDA_SWD_EN_R: R12.2 R13.1 R19.2 U2.5(DIR)
SDA_SWD_OE: R3.1 R33.1 U9.4(Y\1\)
SDA_SWD_OE_B: R28.2 TP50.1(PIN1) U5.20(ADC0_SE8/TSI0_CH0/PTB0/I2C0_SCL)
SDA_SWD_OE_B_R: R27.1 R28.1 U9.3(A2)
SDA_SWD_OE_R: R33.2 R37.2 R39.1 U12.5(DIR)
SDA_USB_CONN_DN: J6.2(P2) R22.1 U4.1(A1)
SDA_USB_CONN_DP: J6.3(P3) R20.1 U6.1(A1)
SDA_USB_DN: R22.2 U5.4(USB0_DM)
SDA_USB_DP: R20.2 U5.3(USB0_DP)
SDA_USB_P5V_SENSE: R7.1 R8.2 U5.30(ADC0_SE6B/PTD5/SPI0_PCS2/U\A\R\)
SDA_USBSHIELD: J6.S1(SHLD1) J6.S2(SHLD2) J6.S3(SHLD3) J6.S4(SHLD4) L1.1
SDA_VOUT33: C11.1 R36.2 TP15.1(PIN1) U5.5(VOUT33)
SDA_XTAL: C6.1 U5.18(XTAL0/PTA19/FTM1_FLT0/FTM_CLKIN) Y1.1
SW1_RST_B: C2.1 J25.2 SW1.2(SW2)
SWD_CLK_KV3X: J11.1 U13.34(PTA0/U\A\R\T\0\_\C\T\S\/FTM0_CH)
SWD_CLK_TGTMCU: J8.2 J9.4(B2) J11.2 TP31.1(PIN1) TP42.1(PIN1)
SWD_CLK_TGTMCU_BUF: J8.1 U2.4(B)
SWD_DIO_TGTMCU: J9.2(B1) J12.2 TP30.1(PIN1) TP41.1(PIN1) U13.37(PTA3/U\A\R\T\0\_\R\T\S\/FTM0_CH)
SWD_DIO_TGTMCU_BUF: J12.1 U10.2(2B) U12.4(B)
TC_EXTAL_TP: TP9.1(PIN1) U5.10(EXTAL32)
TC_SDA_USB_ID_TP: J6.4(P4) TP7.1(PIN1)
TC_XTAL_TP: TP10.1(PIN1) U5.9(XTAL32)
THER_A: C21.1 R45.2 R47.2 RT1.1
THER_B: C21.2 R44.1 R46.2 RT1.2
TP_2102_A: TP3.1(PIN1) U3.3(A2)
TP_2102_B: TP2.1(PIN1) U3.6(B2)
TRACE_SWO: J9.6(B3) R80.1
UART0_RX_TGTMCU: R24.2 R54.2 TP39.1(PIN1)
UART0_TX_TGTMCU: R38.2 R55.1 TP40.1(PIN1)
UART1_RX_PKYK: R59.2 U13.2(PTE1/LLWU_P0/ADC1_SE5A/SPI1_SOU)
UART1_RX_TGTMCU_BUF: R24.1 U7.4(B)
UART1_RX_TGTMCU_R: TP49.1(PIN1) U5.25(PTC4/SPI0_PCS0/UART1_TX/FTM0_CH) U7.3(A)
UART1_TX_PKYK: R58.1 U13.1(PTE0/CLKOUT32K/ADC1_SE4A/SPI1_P)
UART1_TX_TGTMCU_BUF: R38.1 U10.1(1B)
UART1_TX_TGTMCU_R: TP48.1(PIN1) U5.24(CMP1_IN1/PTC3/SPI0_PCS1/UART1_R) U10.6(1A)
V_TGTMCU: C7.1 C23.1 R2.1 R11.1 SH1.1 TP44.1(PIN1) U2.6(VCCB) U3.8(VCCB) U7.6(VCCB) U10.8(VCCB) U12.6(VCCB)
VREFH: C33.1 C34.1 D7.C(CATHODE) R53.1 R66.2 R68.2 U13.23(VREFH)
VREFL: C33.2 C34.2 R62.2 U13.24(VREFL)
VTRG_EN: R29.2 R30.1 R34.2 U11.3(ENABLE)
VTRG_FAULT_B: R35.2 U5.32(PTD7/CMT_IRO/UART0_TX/FTM0_CH7/) U11.4(F\A\U\L\T\)
XTAL0: C38.2 R52.2 TP36.1(PIN1) U13.51(PTA19/XTAL0/FTM0_FLT0/FTM1_FLT0) X501.3
N20314503: R42.1 R64.1 U8.16(RST)
N20919516: R54.1 U13.62(PTB16/SPI1_SOUT/UART0_RX/FTM_CL)
N20919519: R55.2 U13.63(PTB17/SPI1_SIN/UART0_TX/FTM_CLK)
N20920203: R65.2 U13.6(PTE5/SPI1_PCS2/LPUART0_RX/FTM3_)
N20920206: R67.1 U13.5(PTE4/LLWU_P2/SPI1_PCS0/LPUART0_)
N20923344: D4.2(COMMON_A) R88.2 TP43.1(PIN1)
N21097088: TP18.1(PIN1) U13.33(PTE26/CLKOUT32K)

Pads without a net: J3 2; J9 7 8 9; J10 7 9; U8 15; U13 44 45 46 57 69 86

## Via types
v1: diameter 0.508, hole 0.254, TOP to BOTTOM, 369 vias
v2: diameter 0.762, hole 0.457, TOP to BOTTOM, 18 vias

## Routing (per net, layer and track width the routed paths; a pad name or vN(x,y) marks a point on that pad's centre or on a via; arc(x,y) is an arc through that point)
GND: length 259.7
  TOP w0.127: TP21.1 35.87,21.64 ; TP21.1 35.87,20.5 ; TP21.1 36.44,21.07 ; 34.15,12.47 TP24.1 ; TP24.1 34.73,13.05 ; TP24.1 34.73,11.9 ; TP24.1 35.3,12.47 ; Y1.2 21.85,37.93 ; Y1.2 20.6,37.54 ; Y1.2 20.6,38.33 ; Y1.2 19.36,37.93 ; 8.69,27.87 U1.2 ; U1.2 8.69,28.95 ; U1.2 9.33,28.41 ; 68.88,27.89 C32.2 68.37,28.4 ; C44.2 39.14,45.18 ; 8.74,27.55 U4.2 9.38,27.01 ; 18.77,38.42 19.04,38.15 v1(19.04,37.94) 19.04,37.71 18.77,37.44 ; 37.74,22.32 37.7,22.28 C37.1 ; C25.2 53.25,31.55 ; C35.2 64.88,31.78 ; C505.2 32.99,45.18 33.03,45.21 ; 26.13,36.89 26.13,36.88 C8.2 ; U5.8 13.49,35.35 U5.33 11.72,37.83 U5.2 ; 11.33,31.99 C15.2 ; 45.71,23.3 C26.2 45.2,23.81
  TOP w0.152: v1(36.58,20.07) 37.68,20.07 C38.1 ; U8.5 v1(47.78,40.09) ; v1(49.49,31.5) 49.49,32.66 49.28,32.86 U8.12
  TOP w0.203: 62.34,16.1 62.59,15.86 62.59,15.86 U13.88 ; C26.2 46.25,23.81 46.44,23.63 47.05,23.63 47.74,22.93 47.74,22.93 U13.49 49.23,21.44 49.23,21.44 49.66,21 ; 56.8,28 56.3,28.5 56.3,28.51 U13.29 54.81,30 54.8,30 53.25,31.55 ; U13.60 52.06,16.92 52.06,16.92 52.16,17.02 ; U6.2 9.47,25.36 v1(9.71,25.12) 9.71,25.13 ; U2.2 v1(34.51,39.76) ; U7.2 v1(32.14,36.04) ; 52.47,23.85 52.06,24.26 52.06,24.27 U13.41 50.57,25.76 50.56,25.76 49.43,26.89 48.52,26.89 C28.2 ; v1(48.78,40.07) 48.77,40.06 48.77,37.32 U8.3 ; v1(10.34,36.44) U5.2 ; U9.2 28,33.38 v1(28,32.65) ; 57.11,12.08 57.01,11.98 57.01,11.97 U13.74 ; 37.74,22.32 36.65,22.32 v1(36.62,22.35) ; U8.13 49.78,33.18 50.16,32.8 v1(50.16,32.1) ; 36.58,20.07 v1(36.58,20.07) ; v1(32.04,29.12) 31.42,29.12 U10.3 31.28,29.18 U10.4 ; U3.4 v1(28.92,40.23) ; C55.2 v1(74.17,7.61) ; U13.9 64,23.91 64,23.91 63.86,23.76 ; U12.2 v1(30.58,32.4) ; 10.05,33.07 v1(10.05,33.06)
  TOP w0.381: C43.2 66.34,8.23 v1(65.5,8.23) ; J6.5 5.17,24.57 v1(5.95,23.79) ; X501.2 v1(39.73,21.22) ; R44.2 v1(78.55,22.57) ; v1(43.53,38.1) 43.51,38.12 42.77,38.12 R31.2 ; C14.2 53.54,33.15 v1(53.53,33.14) ; 11.12,30.73 v1(11.12,30.71) 11.85,31.45 C15.2 ; C3.2 52.09,42.33 v1(52.35,42.33) ; 38.83,12.3 38.92,12.3 v1(38.9,12.28) ; 18.77,38.42 C6.2 ; SW1.1 v1(3.97,48.18) ; C2.2 v1(10.19,47.39) ; R16.2 34.82,36.95 v1(35.67,36.95) ; v1(8.4,35.16) C10.2 ; C18.2 v1(14.59,24.85) ; 18.77,37.44 C9.2
  TOP w0.508: v1(7.03,36.96) 7.03,35.92 C11.2 ; R60.2 60.98,35.57 60.99,35.59 61.27,35.59 61.28,35.58 v1(61.3,35.58) ; v1(73.18,10.01) 73.18,10.06 TP22.1 ; C23.2 31,25.71 v1(31,24.9) ; C52.2 12.21,7.81 12.37,7.81 v1(12.95,8.38) ; R7.2 5.94,38.92 v1(5.94,39.76) ; C56.2 67.69,46.09 v1(67.98,46.37) ; v1(5.35,33.2) 5.33,33.19 L1.2 ; C7.2 v1(34.67,38.04) ; C5.2 53.58,41.79 52.8,41.79 v1(52.35,41.34) 52.14,41.13 52.05,41.13 C4.2 ; v1(26.97,31.33) 25.91,31.33 R30.2 ; R39.2 33.96,30.79 v1(34.79,30.79) ; C507.2 42.09,45.71 v1(41.81,45.98) ; SW2.2 v1(76.85,48.08) ; C12.2 11.48,32.87 v1(10.9,32.29) ; v1(64.27,33) 63.68,32.4 C27.2 ; C35.2 64.87,31.27 v1(64.87,32.16) ; C41.2 v1(4.79,15.34) ; SW3.2 v1(76.85,5.23) ; v1(36.05,46.11) 36.05,45.19 C516.2 ; v1(52.86,8.88) 52.88,8.88 52.97,8.78 53.58,8.78 C29.2 ; C53.2 v1(2.3,7.15) ; R6.2 20.71,33.52 v1(20.42,33.81) ; C1.2 10.66,33.67 v1(10.05,33.06) ; C522.2 45.19,45.13 v1(46.39,45.13) ; C17.2 29.58,25.86 v1(28.78,25.86) ; R43.2 44.32,33.31 C13.2 43.72,33.34 v1(43.55,33.51) ; C54.2 v1(13.19,6.24) ; v1(65.68,12.41) 65.97,12.41 C30.2 ; C51.2 v1(16.85,22.32) ; U11.2 v1(25.99,28.7) ; 33.03,45.21 v1(33.03,46.06) ; v1(61.93,34.84) R62.1 ; 39.14,45.18 39.14,45.94 v1(39.03,46.05) ; v1(30.34,36.09) R13.2 ; C16.2 v1(28.77,27.62) ; C22.2 v1(66.81,30.26) ; v1(25.39,36.97) 26.04,36.97 26.13,36.89 ; TP23.1 78.92,36.76 78.92,37.61 v1(78.88,37.65) ; C32.2 68.39,27.9 v1(68.39,28.78) ; v1(54.45,39.25) R42.2 ; D7.A v1(58.24,41.07) ; v1(47.87,13.11) 48.8,13.11 C24.2 ; C50.2 12.2,9.47 v1(13.07,9.47) ; v1(6.55,18.54) U17.1 v1(9.08,20.48) ; C40.2 v1(35.25,7.94)
  GND w0.127: TP16.1 15.02,9.97 ; TP16.1 14.07,9.02 ; TP16.1 15.02,8.07 ; TP16.1 15.97,9.02 ; J2.14 27.52,50.83 ; J2.14 25.46,50.83 ; J2.14 26.49,51.85 ; 6.08,2.93 J27.2 ; J27.2 7.99,2.93 ; J27.2 7.03,1.98 ; J27.2 7.03,3.88 ; J3.14 43.14,3.61 ; J3.14 42.11,2.58 ; J3.14 44.17,2.58 ; 39.57,2.58 J3.12 ; J9.3 76.54,34.29 ; 15.18,26.02 J10.5 ; 13.91,26.02 J10.3 ; J9.5 76.54,35.56 ; 26.49,49.8 26.49,50.82 ; 40.6,1.55 40.6,2.57 ; 40.6,3.61 40.6,2.58 ; 41.63,2.58 40.61,2.58 ; 43.14,1.55 43.14,2.57
  GND w0.152: 72.49,19.32 72.49,19.3
  GND w0.381: TP16.1 15.99,8.05 ; TP16.1 14.06,8.06 ; TP16.1 14.03,10.01 ; TP16.1 16.11,10.1 16.16,10.1 ; 24.39,5.4 J24.2 ; J24.2 23.47,7.64 ; J24.2 25.84,7.64 ; J24.2 24.39,10.01 ; 6.12,2.02 J27.2 ; J27.2 6.11,3.86 ; J27.2 7.89,2.07 ; J27.2 7.86,3.75 ; J24.3 18.39,10.56 ; J24.3 17.2,8.64 ; J24.3 18.39,6.59 ; J24.3 19.65,8.64 19.65,8.64 ; 26.49,50.82 J2.14 ; J2.14 25.59,49.92 ; J2.14 27.64,51.97 ; J2.14 27.5,49.81 ; J2.14 25.46,51.86 ; 43.14,2.57 J3.14 ; J3.14 44.04,1.68 ; J3.14 42.28,1.72 ; J3.14 44.18,3.62 ; J3.14 42.2,3.52 ; 41.56,3.54 J3.12 ; J3.12 39.69,3.49 ; J3.12 41.45,1.73 ; J3.12 40.61,2.58 ; J3.12 40.6,2.57 ; J3.12 39.74,1.72 ; J3.12 40.6,2.58
  INT_1 w0.127: 23.47,7.64 J24.2 ; J24.2 24.39,9.56 ; J24.2 25.3,7.64 ; J24.2 24.39,5.72 ; J2.14 27.52,50.83 ; J2.14 26.49,49.8 ; J2.14 26.49,51.85 ; J2.14 25.46,50.83 ; TP16.1 15.97,9.02 ; TP16.1 15.02,8.07 ; TP16.1 14.07,9.02 ; TP16.1 15.02,9.97 ; J27.2 7.03,3.88 ; J27.2 6.08,2.93 ; J27.2 7.03,1.98 ; J27.2 7.99,2.93 ; 75.86,33.62 J9.3 ; J9.3 75.19,34.29 ; J9.3 76.54,34.29 ; J9.5 76.54,35.56 ; J9.5 75.19,35.56 ; J9.5 75.86,36.23 ; 18.39,6.72 J24.3 ; J24.3 17.47,8.64 ; J24.3 18.39,10.56 ; J24.3 19.3,8.64 ; 13.91,26.02 J10.3 ; 40.6,1.55 J3.12 ; J3.12 39.57,2.58 ; J3.12 41.63,2.58 ; J3.12 40.6,3.61 ; 43.14,1.55 J3.14 ; J3.14 42.11,2.58 ; J3.14 43.14,3.61 ; J3.14 44.17,2.58 ; 15.18,26.02 J10.5
  BOTTOM w0.127: 6.08,2.93 J27.2 ; J27.2 7.99,2.93 ; J27.2 7.03,1.98 ; J27.2 7.03,3.88 ; TP16.1 15.97,9.02 ; 26.49,51.85 26.49,50.83 ; J2.14 27.52,50.83 ; 18.39,10.56 18.39,10.48
  BOTTOM w0.381: TP16.1 15.02,9.03 14.33,9.72 ; TP16.1 15.83,9.83 ; TP16.1 14.99,9.02 14.33,8.36 ; TP16.1 15.02,9.01 15.68,8.36 ; 18.39,10.48 J24.3 ; J24.3 18.39,6.72 ; J24.3 17.47,8.64 ; J24.3 19.3,8.64 ; J24.2 24.39,5.72 ; J24.2 23.47,7.64 ; J24.2 24.39,9.6 ; J2.14 26.48,50.83 25.67,51.64 ; J2.14 26.49,50.83 ; J2.14 26.49,50.82 25.67,49.99 ; 6.04,3.92 J27.2 ; J27.2 6.15,2.05 ; J27.2 7.93,2.03 ; J27.2 7.8,3.7
  vias: v1(1.22,15.11) v1(1.25,11.23) v1(1.77,48.21) v1(1.79,43.59) v1(1.81,46.2) v1(1.86,40.81) v1(4.27,32.26) v1(5.97,25.52) v1(6,27) v1(7.03,1.28) v1(7.27,24.25) v1(7.64,33.62) v1(7.96,30.78) v1(9.01,52.12) v1(9.92,28.41) v1(10.05,30.65) v1(10.57,24.25) v1(11.58,44.65) v1(11.5,1.07) v1(12.78,38.48) v1(12.79,37.1) v1(14.24,38.5) v1(14.27,37.12) v1(17.41,51.98) v1(17.52,46.7) v1(18.84,40.07) v1(19.17,36) v1(19.15,0.99) v1(19.36,44.06) v1(20.54,40.07) v1(20.69,35.99) v1(24.3,46.5) v1(24.84,1.14) v1(27.03,46.56) v1(29.78,46.54) v1(31.6,23.44) v1(31.54,20.67) v1(31.54,14.5) v1(32.64,11.57) v1(33.56,27.99) v1(33.53,25.33) v1(33.55,15.55) v1(36.74,18.63) v1(39.52,13.9) v1(39.8,23.75) v1(39.89,18.58) v1(43.04,18.54) v1(43.17,23.77) v1(43.55,12.24) v1(44.83,13.78) v1(45.7,23.01) v1(45.75,18.61) v1(47.88,11.52) v1(48.07,1.53) v1(48.2,6.34) v1(50.28,20.72) v1(52.6,46.66) v1(52.76,17.01) v1(52.98,23.2) v1(54.15,20.26) v1(55.9,14.21) v1(56.33,24.62) v1(57.11,27.63) v1(57.73,12.33) v1(58.14,20.99) v1(60.05,14.39) v1(60.3,20.08) v1(60.54,23.36) v1(61.03,26.09) v1(61.81,16.31) v1(63.45,23.31) v1(65.49,21.48) v1(66.85,32.45) v1(71.46,44.26) v1(71.52,40.99) v1(72.09,51.98) v1(73.78,44.24) v1(73.81,41.01) v1(73.87,27.52) v1(76,44.26) v1(76.15,40.97) v1(76.45,29.34) v1(78.29,44.28) v1(78.36,41.03) v1(79.38,29.44) v1(79.8,25.47)
P3V3: length 67.3
  TOP w0.152: 26.74,22.13 J20.1 ; J20.1 28.64,22.13 ; J20.1 27.69,23.09 ; D11.C 22.37,17.16 ; 23.38,19.58 J18.2 ; R63.1 29.99,21.92 ; R63.1 29.48,21.41 ; R63.1 30.5,21.41 ; R61.1 22.76,20.1
  TOP w0.203: U8.1 49.8,37.34 49.8,40.07 v1(49.8,40.07) ; U8.14 v1(52.83,35.54)
  TOP w0.381: R40.1 42.76,33.03 R32.1 43.14,34.06 43.45,34.38 v1(43.46,34.38) ; 28.68,23.12 J20.1 26.7,23.12 ; v1(67.13,8.82) 67.7,8.25 R50.1 ; R15.1 v1(56.2,40.19) ; v1(54.63,34.99) 54.6,34.96 C14.1 52.96,35.54 v1(52.83,35.54) ; 29.46,21.94 R63.1 30.52,21.94 ; v1(49.8,40.07) 50.26,40.53 C4.1 50.46,40.51 50.46,39.96 50.88,39.55 52.29,39.55 52.85,40.1 C5.1 v1(54.95,40.1) 54.95,40.95 R9.1 ; R48.1 43.67,16.45 43.06,16.45 43,16.4 v1(42.89,16.4) ; R75.1 v1(74.21,6.42) ; 27.78,23.77 SH1.2 26.96,24.53 ; 24.86,18.56 24.86,19.05 24.33,19.58 J18.2 23.5,18.75 ; R49.1 v1(70.2,8.23) ; v1(42.87,15.48) R41.1
  TOP w0.508: 27.06,23.81 SH1.2 ; v1(22.37,14.88) D11.C v1(24.19,16.27) ; R1.1 v1(69.51,44.28) ; v1(75.88,23.57) 76.86,23.57 R45.1 ; v1(73.75,20.21) 73.35,19.81 R88.1 ; R61.1 22.25,19.81 22.65,19.41 ; C40.1 32.73,7.94 v1(32.73,6.52)
  BOTTOM w0.127: 29.41,2.58 J3.4 30.44,3.61 ; J20.1 28.64,22.13 ; J20.1 26.74,22.13 ; J20.1 27.69,23.09 ; 19.08,22.15 J19.1 20.99,22.15 ; 24.33,18.63 J18.2 ; 34.49,2.58 J3.8
  BOTTOM w0.381: J3.8 35.52,3.55 ; J3.8 36.68,2.58 36.68,2.58 ; J3.8 34.63,3.47 ; J3.4 31.58,2.58 ; J3.4 29.6,3.42 ; J3.4 31.34,3.48 ; 19.15,23.23 19.15,23.04 J19.1 20.04,22.19 20.91,23.07 ; 23.09,19.58 J18.2 23.38,18.63
  vias: v1(24.46,17.9)
P3V3_KV31: length 48.1
  TOP w0.152: 64.4,14.75 64.42,14.75 64.45,14.72 ; 60.87,29.97 60.87,29.97 60.9,30 ; 65.85,25.05 65.82,25.02 65.82,25.02
  TOP w0.203: U13.22 60.87,29.97 ; 60.9,30 62.19,31.29 62.58,31.29 62.96,31.68 ; v1(51.68,30.84) 51.69,30.83 53.27,30.83 54.46,29.65 U13.30 ; 64.45,14.72 C30.1 65.26,13.14 65.11,13.14 v1(65.01,13.04) ; v1(48.77,14.08) 48.78,14.09 49.33,14.09 49.54,13.87 C24.1 49.68,13.85 51.65,15.82 U13.61 ; 48.84,22.54 48.82,22.54 46.83,24.53 C26.1 ; U13.8 65.82,25.02 ; v1(54.52,8.8) 54.32,9.01 C29.1 55.27,9.53 U13.75 ; 65.85,25.05 66.62,25.81 66.62,26.13 C32.1 ; U13.89 64.4,14.75 ; v1(48.05,27.97) 48.88,27.97 C28.1 49.52,27.33 49.74,27.33 51.67,25.4 U13.40
  TOP w0.381: R63.2 28.49,20.39 J20.2 ; C26.1 46.32,24.53 v1(45.77,25.08) ; 62.96,31.68 63.55,31.1 v1(63.56,31.1) ; C32.1 66.89,27.94 66.89,27.95 v1(66.48,28.35)
  TOP w0.508: v1(60.94,43.68) 60.96,43.68 60.97,43.68 61.9,43.68 R66.1 62.2,43.38 62.56,43.38 62.84,43.1 R68.1 ; v1(35.04,18.38) 35.04,19.24 TP37.1
  BOTTOM w0.127: J20.2 28.64,19.59 ; J20.2 26.74,19.59 ; J20.2 27.69,18.64 ; 75.86,32.35 J9.1 76.54,33.02
  BOTTOM w0.203: J9.1 75.13,32.29
  BOTTOM w0.381: 26.88,18.78 J20.2 28.54,18.75
  vias: v1(25.97,18.49)
P3V3_SDA: length 40.7
  TOP w0.127: 23.38,22.12 J18.1 ; J18.1 24.33,21.17 ; J18.1 24.33,23.07 ; 24.34,22.12 25.28,22.12
  TOP w0.203: U10.7 30.18,27.26 C17.1 ; U5.11 14.66,35.6 v1(15.3,34.96) ; R14.1 28.25,37.54 28.27,37.56 U3.1 ; v1(31.74,31.7) 31.73,31.71 U12.1 ; U7.1 32.73,36.54 v1(32.23,37.03) ; 12.64,25.58 12.64,25.49 12.74,25.4 ; U5.7 12.21,34.77 C12.1 12.21,33.27 C15.1 ; v1(34.52,38.94) 34.21,39.26 U2.1 ; U9.5 v1(27.99,34.85) ; C10.1 9.85,36.66 10.14,36.95 10.14,36.95 U5.1
  TOP w0.381: R27.2 21.59,34.36 TP38.1 20.53,34.5 v1(20.22,34.81) ; R4.2 27.05,40.85 v1(27.05,39.98) ; v1(34.04,32.24) 34.04,33.09 R23.1 ; 25.23,23.02 24.34,22.12 J18.1 23.4,23.05 ; v1(13.28,31.15) 13.54,31.4 13.54,31.94 C15.1 ; 22.25,21.71 R61.2 22.78,21.12 ; 12.74,25.4 C18.1 ; R35.1 19.92,27.75 19.43,27.75 v2(18.84,28.34) ; C17.1 28.79,26.76 v2(28.78,26.75) ; J10.1 12.64,25.58 ; v1(27.69,37.61) 27.63,37.61 27.25,37.23 C8.1 28.14,36.88 R14.1 ; R12.1 30.48,38.56 v2(30.48,39.33) ; R37.1 v1(34.72,29.63) ; v1(26.84,34.69) 26.57,34.42 R26.1 ; v2(22.27,22.72) 22.29,22.74
  TOP w0.508: R17.1 2.96,35.8 R36.1 4.64,36.91 v2(4.63,36.92) ; v1(8.39,37.39) 9.12,36.66 C10.1 ; R21.1 v1(20.22,34.81)
  BOTTOM w0.127: 11.97,26.69 J10.1 12.64,26.02
P3V3_VREG: length 20.9
  TOP w0.152: 15.44,20.16 C51.1 ; C51.1 16.2,20.79 ; C51.1 14.68,20.79 ; 19.82,15.38 D11.A ; D11.A 20.47,16.27 ; D11.A 19.82,17.16 ; D11.A 19.18,16.27 ; TP56.1 18.31,18.13 ; TP56.1 17.17,18.13 ; TP56.1 17.74,18.7 ; TP56.1 17.74,17.55 ; U17.4 15.28,18.29 ; U17.4 15.28,14.18 ; U17.4 16.58,16.24 ; 19.08,19.61 J19.2 ; J19.2 20.99,19.61 ; J19.2 20.04,18.66
  TOP w0.381: 19.18,18.76 J19.2 20.83,18.82
  TOP w0.508: U17.2 10.44,16.24 ; U17.4 13.83,16.24
  vias: v2(12.88,19.46) v2(12.92,17.02) v2(13.01,14.01) v2(15.27,19.49) v2(17.39,19.47) v2(17.42,17.02) v2(17.46,14.02) v2(19.97,14.02)
P5V0_SDA_USB_CONN_VBUS: length 6.5
  TOP w0.381: J6.1 5.23,27.17 6.47,28.41 U1.1 ; 6.88,30.94 L2.1
  TOP w0.508: L2.1 6.88,29.83 7.39,29.32 U1.1
P5V_OPT_VR: length 10.6
  TOP w0.152: 4.49,1.98 J27.3 3.54,2.93 ; D13.A 5.04,6.92 ; C53.1 3.82,6.78
  TOP w0.381: 3.82,3.62 4.49,2.95 J27.3 ; J27.3 5.25,3.68 ; J27.3 4.5,2.93 5.22,2.2 ; J27.3 3.71,2.15 ; C53.1 3.82,5.26
  TOP w0.508: 5.04,5.15 D13.A 5.02,6.02 C53.1
P5V_SDA: length 15.9
  TOP w0.203: U5.6 11.91,35.18 11.91,34.93 C1.1 11.38,33.54 v1(9.74,31.91)
  TOP w0.381: R8.1 5.93,37.43 v1(6.18,37.18) ; v1(24.16,26.78) 24.4,26.54 C19.1 ; C16.1 26.96,28.32 27.8,29.15 27.8,29.32 27.81,29.33 27.85,29.38 27.86,29.43 R34.1 ; C16.1 26.33,27.62 26.2,27.75 U11.1 ; C16.1 26.96,26.94 27.03,26.88 v1(27.03,26.87) ; v1(20.99,31.1) 20.91,31.1 20.71,31.31 R5.1
  TOP w0.508: R8.1 5.17,37.92 TP12.1 ; L2.2 6.85,32.29 6.85,33.14 v2(6.68,33.3)
P5V_SDA_PSW: length 8.7
  TOP w0.152: 5.7,11.19 D6.A 4.4,11.19 ; TP19.1 2.6,15.4 ; TP19.1 2.6,14.25 ; TP19.1 3.18,14.82 ; TP19.1 2.03,14.82 ; 4.4,8.6 D5.A 5.7,8.6
  TOP w0.381: 22.28,27.25 U11.6 21.52,27.75
  TOP w0.508: D6.A D5.A
P5V_USB: length 36.2
  TOP w0.635: D13.C v2(7.59,7.3) 7.59,8.59 D5.C
  INT_1 w0.508: J3.10 38.06,2.56 36.67,1.17 26.72,1.17 23.17,4.72 19.1,4.72 16.6,7.22 7.67,7.22 v2(7.59,7.3)
VSSA: length 5.3
  TOP w0.203: U13.25 59.84,31.06 60.29,31.51 60.29,32.84 59.66,33.47 R60.1
8MHZ_EXTAL: length 10
  TOP w0.152: U13.50 47.4,22.56 47.4,22.56 47.14,22.83 46.76,22.83 45.94,22.01 45.37,22.01 45.36,22.02 TP35.1 44.61,21.86 R52.1 42.84,22.42 X501.1 41.21,22.37 39.33,22.37 39.23,22.27 C37.2
ADC0_DM0: length 35.2
  TOP w0.152: v1(62.74,29.65) 62.43,29.34 62.36,29.34 61.93,28.91 U13.19
  INT_1 w0.152: J4.5 51.58,9.45 51.58,12.97 64.91,26.3 64.91,27.93 64.23,28.61 63.78,28.61 v1(62.74,29.65)
ADC0_DM1: length 35
  TOP w0.152: U13.15 63.57,27.72 63.68,27.72 v1(63.99,28.03)
  INT_1 w0.152: J4.3 49.6,8.9 49.6,15.58 51.84,17.82 55.75,17.82 64.45,26.52 64.45,27.57 v1(63.99,28.03)
ADC0_DP0: length 41.6
  TOP w0.152: v1(60.21,27.02) 60.74,27.02 U13.18 ; R76.1 37.71,43.23 C44.1 39.18,43.22 39.18,42.3 39.99,41.49 45.61,41.49 48.05,43.93 57.22,43.93 v1(57.95,43.2)
  INT_1 w0.152: v1(60.21,27.02) 59.89,27.34 59.89,41.26 v1(57.95,43.2)
ADC0_DP0_RC: length 4.5
  TOP w0.152: R76.2 37.69,45.99 36.65,47.03 J2.5
ADC0_DP1: length 29.6
  TOP w0.152: v1(61.85,25.4) 61.96,25.4 U13.14
  INT_1 w0.152: v1(61.85,25.4) 54.75,18.31 51.53,18.31 49.21,15.99 49.21,6.75 J4.1
ADC1_DM0: length 38.6
  TOP w0.152: U13.21 61.86,30.26 61.87,30.26 62.23,30.62 v1(62.49,30.62)
  INT_1 w0.152: v1(62.49,30.62) 62.8,30.3 63.05,30.3 65.38,27.98 65.38,26.02 52.17,12.81 52.17,12.11 55.83,8.45 57.48,8.45 58.46,7.47 J4.7
ADC1_DM1: length 10.3
  TOP w0.152: R46.1 68.73,31.29 68.73,31.64 68.41,31.95 66.39,31.95 64.99,30.55 C35.1 63.93,30.32 63.93,29.49 62.65,28.21 62.65,28.21 U13.17
ADC1_DP0: length 37.1
  TOP w0.152: R551.1 41.05,43.17 41.07,43.15 C507.1 42.09,42.45 42.69,41.85 45.41,41.85 47.83,44.26 57.97,44.26 v1(58.66,43.58) ; U13.20 60.88,28.55 v1(61.93,29.59)
  INT_1 w0.152: v1(58.66,43.58) 60.37,41.86 60.37,31.85 61.4,30.83 61.92,30.3 61.92,30.06 61.93,30.05 v1(61.93,29.59)
ADC1_DP0_RC: length 4.7
  TOP w0.152: R551.2 40.61,45.55 39.19,46.97 J2.3
ADC1_DP1: length 9.4
  TOP w0.152: R47.1 68.44,31.18 68.44,31.43 68.23,31.64 66.5,31.64 65.24,30.38 C22.1 64.84,29.14 64.28,29.14 62.99,27.85 62.99,27.85 U13.16
ADC1_SE18: length 37.2
  TOP w0.152: v1(33.04,42.28) 33.05,42.29 33.05,43.12 C505.1 31.95,43.25 31.94,43.27 R534.1 ; U13.26 55.89,31.04 55.89,31.05 54.38,32.56 51.78,32.56 49.99,30.77 44.02,30.77 43.35,31.45 42.55,31.45 42,31.99 41.44,31.99 v1(40.5,32.93)
  INT_1 w0.152: v1(33.04,42.28) 38.83,42.28 40.66,40.45 40.66,33.87 40.5,33.72 v1(40.5,32.93)
ADC1_SE18_RC: length 4.1
  TOP w0.152: R534.2 31.4,46.45 31.57,46.62 J2.9
ADC1_SE23: length 43.5
  TOP w0.152: v1(41.93,31.28) 42.26,30.96 43.28,30.96 43.83,30.41 50.16,30.41 51.93,32.18 53.33,32.18 53.44,32.07 53.45,32.07 53.75,31.77 53.75,31.76 55.17,30.33 55.18,30.33 U13.28
  INT_1 w0.152: v1(41.93,31.28) 41.93,43.95 39.13,46.76 30.56,46.76 J2.11
AREF: length 52
  TOP w0.381: R53.2 66.27,43.13 66.27,45.15 65.15,46.27 65.15,51.13 63.96,52.31 25.44,52.31 J2.16
DAC0_OUT: length 59.7
  TOP w0.152: v1(57.78,34.86) 59.01,36.09 63.21,36.09 63.59,35.7 66.35,32.95 68.88,32.95 70.95,30.87 72.93,30.87 v1(73.42,30.39) ; v1(57.78,31.14) 57.78,29.64 57.37,29.23 56.99,29.23 U13.27 ; C43.1 65.94,6.78 65.2,6.78 J4.11
  INT_1 w0.152: v1(73.42,30.39) 73.42,29.93 73.42,29.93 73.42,27.71 73.41,27.71 73.41,27.33 73.42,27.32 73.42,25.5 72.89,24.98 72.89,24.83 72.89,24.83 72.89,24.45 72.89,24.45 72.89,22.62 69.49,19.22 69.49,11.96 66.62,9.08 64.94,9.08 63.54,7.68 J4.11 ; v1(57.78,31.14) v1(57.78,34.86)
DC_JACK: length 5.9
  TOP w0.508: D9.A 25.73,9.59 25,10.31 21.87,10.31 J24.1
FXOS8700CQ_CRST: length 4.6
  TOP w0.203: C13.1 44.08,34.56 v1(44.08,35.34) 44.28,35.54 U8.8
FXOS8700CQ_I2C_SA0: length 8.1
  TOP w0.152: R32.2 43.26,35.57 v1(43.26,36.04) ; v1(43.26,36.04) 42.74,36.55 R31.1 ; v1(43.26,36.04) 42.07,36.04 TP8.1
  TOP w0.203: U8.7 v1(43.26,36.04)
FXOS8700CQ_I2C_SA1: length 9.6
  TOP w0.152: U8.10 48.3,34.74 v1(48.3,31.42) 48.17,31.3 46.58,31.3 TP11.1 45.59,31.3 44.41,31.3 R43.1 43.69,32.01 R40.2
I2C0_SCL_PKYK: length 5.5
  TOP w0.152: R56.1 67.87,15.52 66.54,16.85 66.54,16.86 U13.95
I2C0_SDA_PKYK: length 6.3
  TOP w0.152: R57.2 70.84,16.09 68.02,16.09 66.9,17.21 66.89,17.21 U13.96
LEDRGB_BLUE: length 5.2
  TOP w0.152: R73.1 74.36,16.46 74.38,16.43 TP14.1 75.61,14.62 D4.3
LEDRGB_GREEN: length 8.3
  TOP w0.152: R74.1 74.76,14.4 75,14.15 75,12.52 75.63,11.89 TP17.1 76.78,11.89 77.5,11.89 78.04,12.43 D4.4
LEDRGB_RED: length 15.8
  TOP w0.152: R69.2 74.19,10.99 75.75,9.43 76.27,9.43 76.27,9.44 TP13.1 78.06,9.44 79.01,10.39 79.01,15.57 78.04,16.54 D4.1
LVLRST_EN: length 1.2
  TOP w0.152: U3.5 28.27,40.64 R4.1
MIC2005_CSLEW: length 4
  TOP w0.152: C19.2 22.88,25.92 23.36,26.4 23.36,28.41 23.07,28.7 U11.5
MMA8451_BYP: length 6.3
  TOP w0.152: TP4.1 49.75,42.32 C3.1 50.02,41.28 49.61,41.28 v1(49.29,40.95) 49.29,37.93 49.28,37.92 U8.2
Net_173: length 3.4
  TOP w0.152: 50.05,36.04 v1(53.43,36.04)
P5-9V_VIN: length 18.1
  TOP w0.127: 8.62,2.93 J27.1 ; J27.1 9.57,1.98 ; J27.1 10.53,2.93 ; J27.1 9.57,3.88 ; 10.04,9.47 C50.1 ; 10.04,6.24 C54.1 ; 10.04,7.79 C52.1
  TOP w0.381: C50.1 10.68,9.47 10.68,10.2
  TOP w0.508: C50.1 C52.1 C54.1 10.67,5.29 ; TP20.1 29.2,8.22 v2(29.49,8.22) 29.49,9.56 D10.A ; 10.67,4.03 J27.1
  BOTTOM w0.127: 45.68,1.55 J3.16
  BOTTOM w0.508: J27.1 9.57,3.98
  BOTTOM w0.635: 44.77,1.67 J3.16
  vias: v2(11.23,10.72)
P5-9V_VIN_VR: length 14.7
  TOP w0.127: D10.C 29.46,13.44 ; D10.C 28.57,12.15 ; D10.C 30.35,12.15 ; 7.79,13.94 U17.3 ; U17.3 9.08,13.15 ; U17.3 10.38,13.94 ; U17.3 9.08,14.72 ; 6.31,14.62 C41.1 6.31,13.1 ; 25.92,12.14 D9.C ; D9.C 27.7,12.14 ; D9.C 26.81,13.43 ; 6.95,13.86 6.33,13.86 ; 8.9,11.19 D6.C 7.6,12.08
  TOP w0.508: 6.33,13.86 C41.1 ; 28.37,12.14 28.38,12.15
POWER_EN: length 19.9
  TOP w0.152: v1(9.78,39.13) 10.42,39.13 10.53,39.02 10.91,38.64 ; R29.1 21.18,30.27 20.48,30.27 19.6,31.15 15.26,31.15 v1(14.51,31.9)
  INT_1 w0.152: v1(9.78,39.13) 9.78,38.16 10.13,37.81 11.11,37.81 14,34.92 14,32.41 v1(14.51,31.9)
PTA2: length 31.2
  TOP w0.152: v1(54.07,25.78) 53.81,26.04 53.81,26.05 U13.36 ; v1(58.28,38.91) 64.85,38.91 65.88,37.87 68.05,37.87 68.07,37.89 TP32.1 R80.2
  INT_1 w0.152: v1(58.28,38.91) 58.28,37.26 58.47,37.07 58.47,27.35 56.89,25.78 v1(54.07,25.78)
